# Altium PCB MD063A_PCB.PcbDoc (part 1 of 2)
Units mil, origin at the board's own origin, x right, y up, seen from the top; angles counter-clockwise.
Board outline 3360 x 2682 mil, 4 copper layers (Top Layer, Signal Layer 1, Signal Layer 2, Bottom Layer), stack 61.6 mil thick; 162 components, 89 nets, 431 pads, 221 vias.
Unrouted connection lines stored in the file: 2.
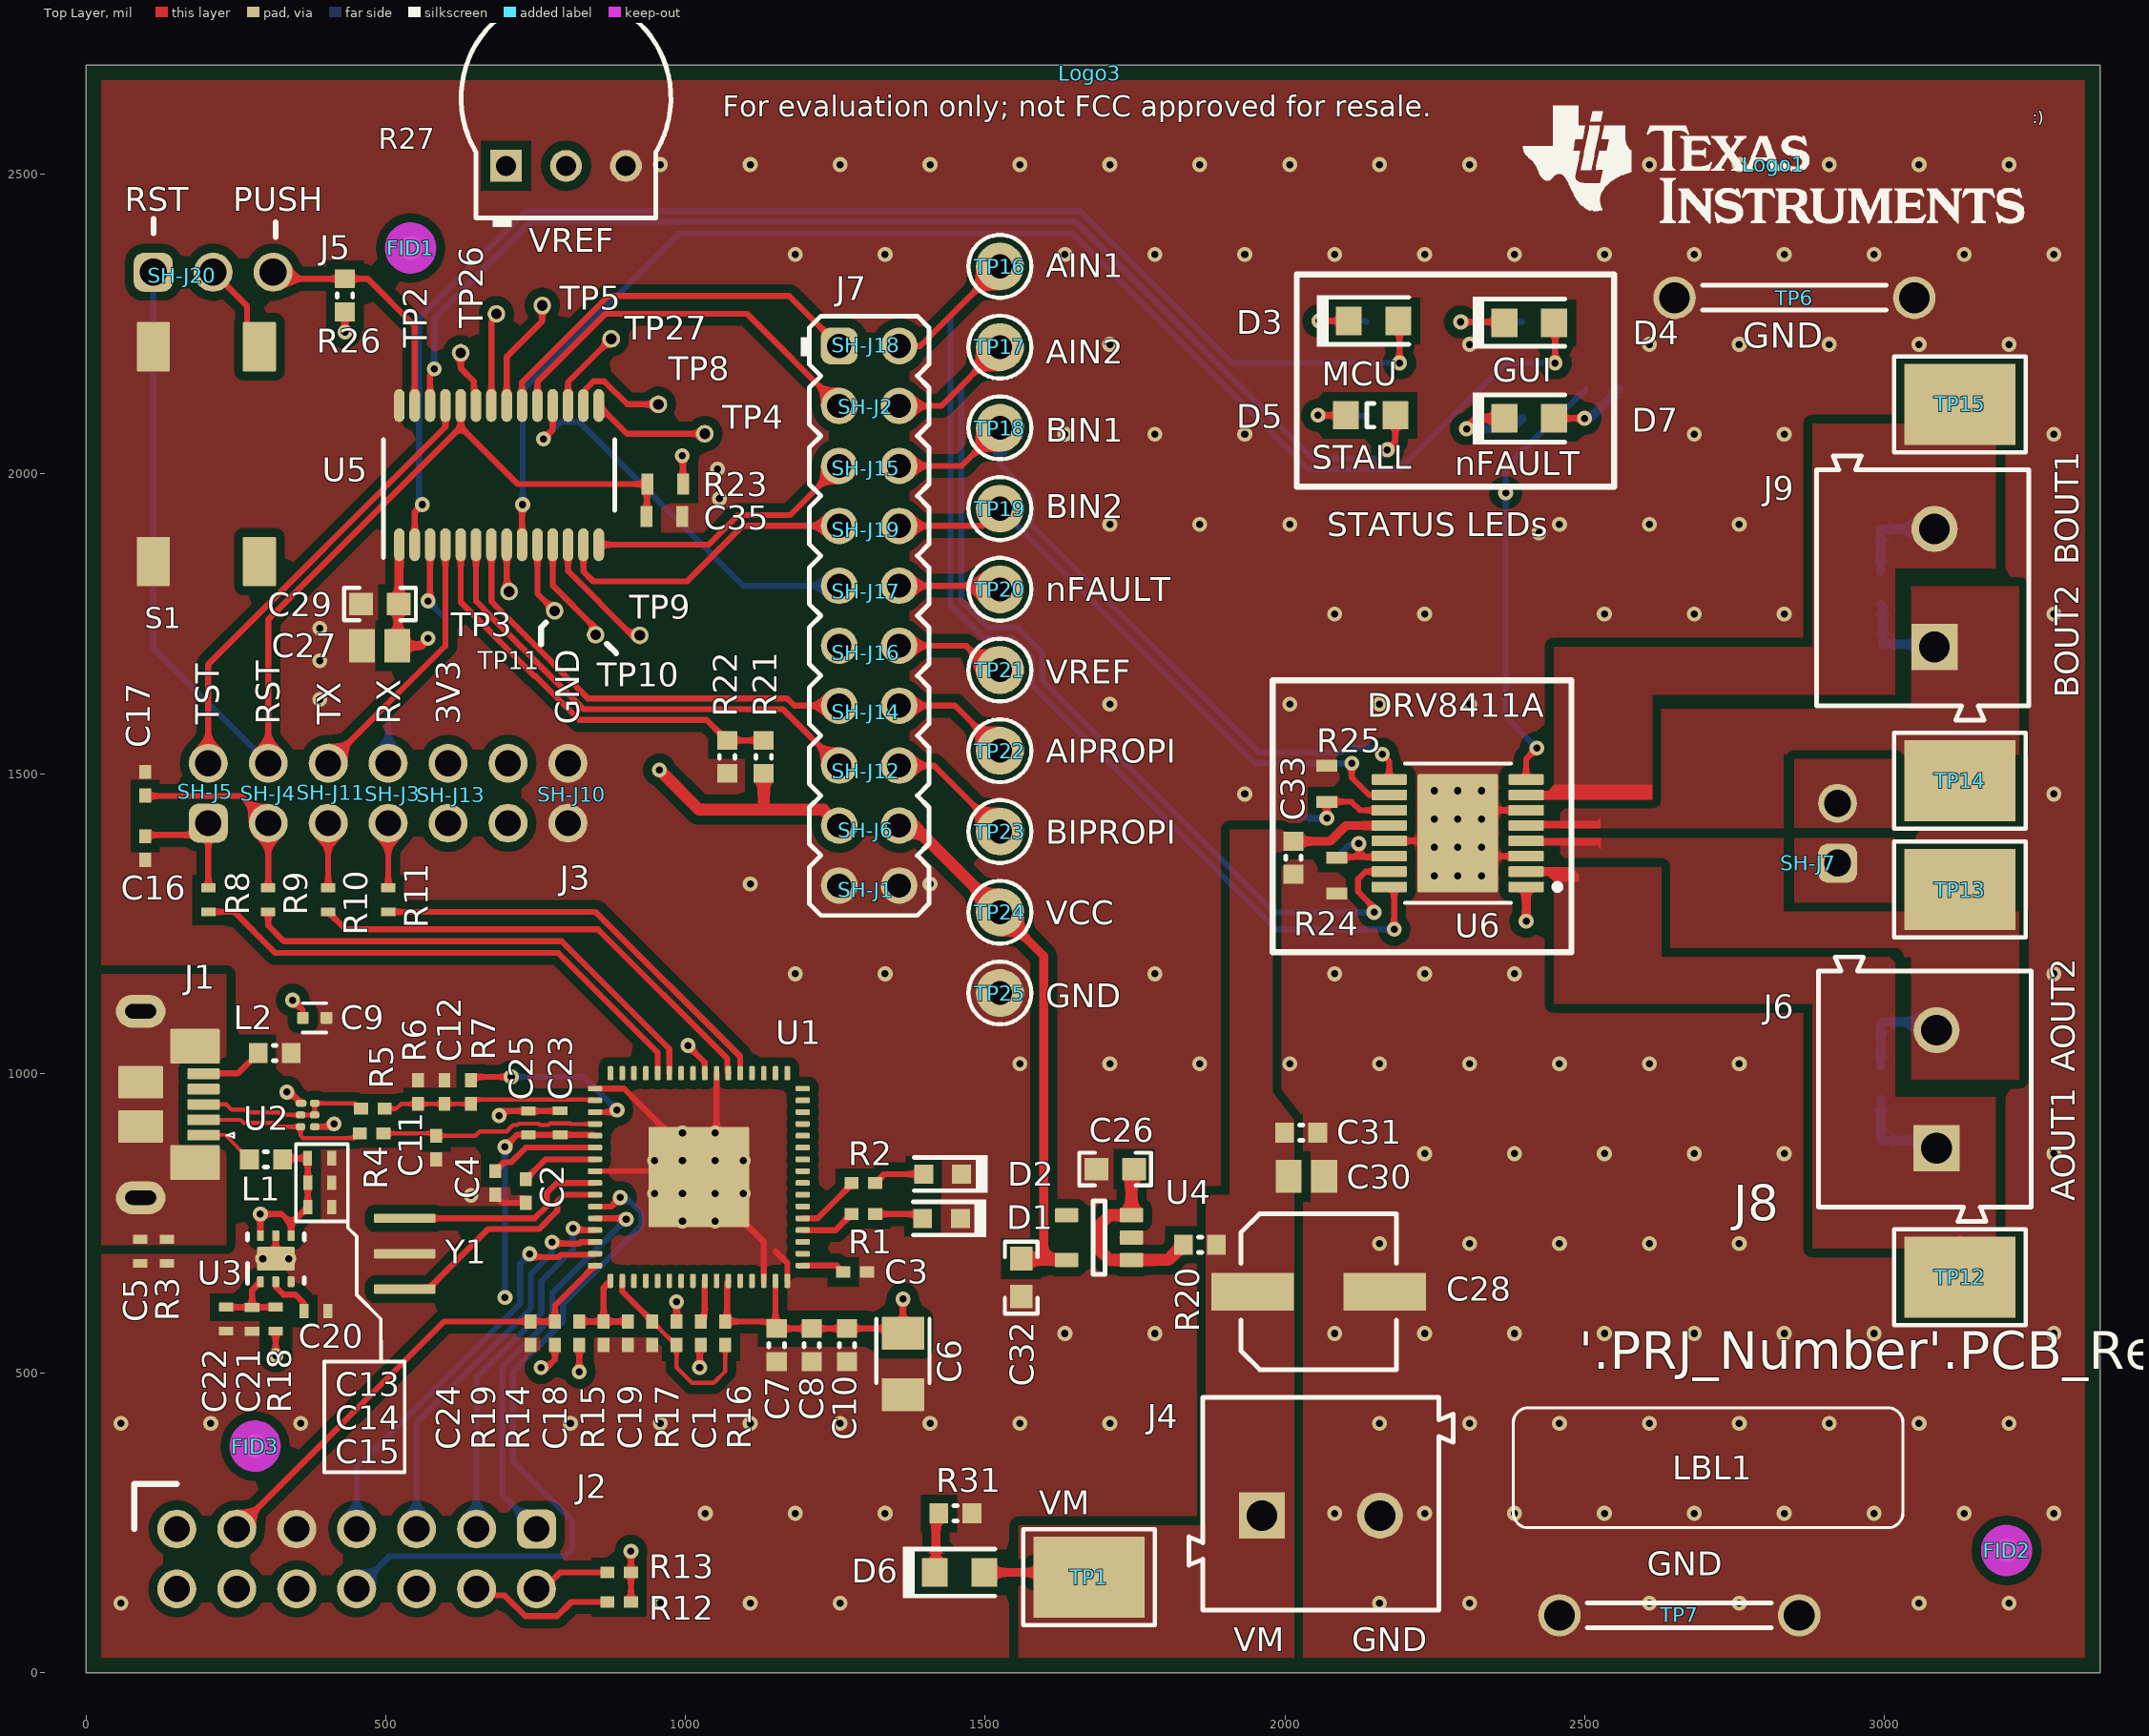
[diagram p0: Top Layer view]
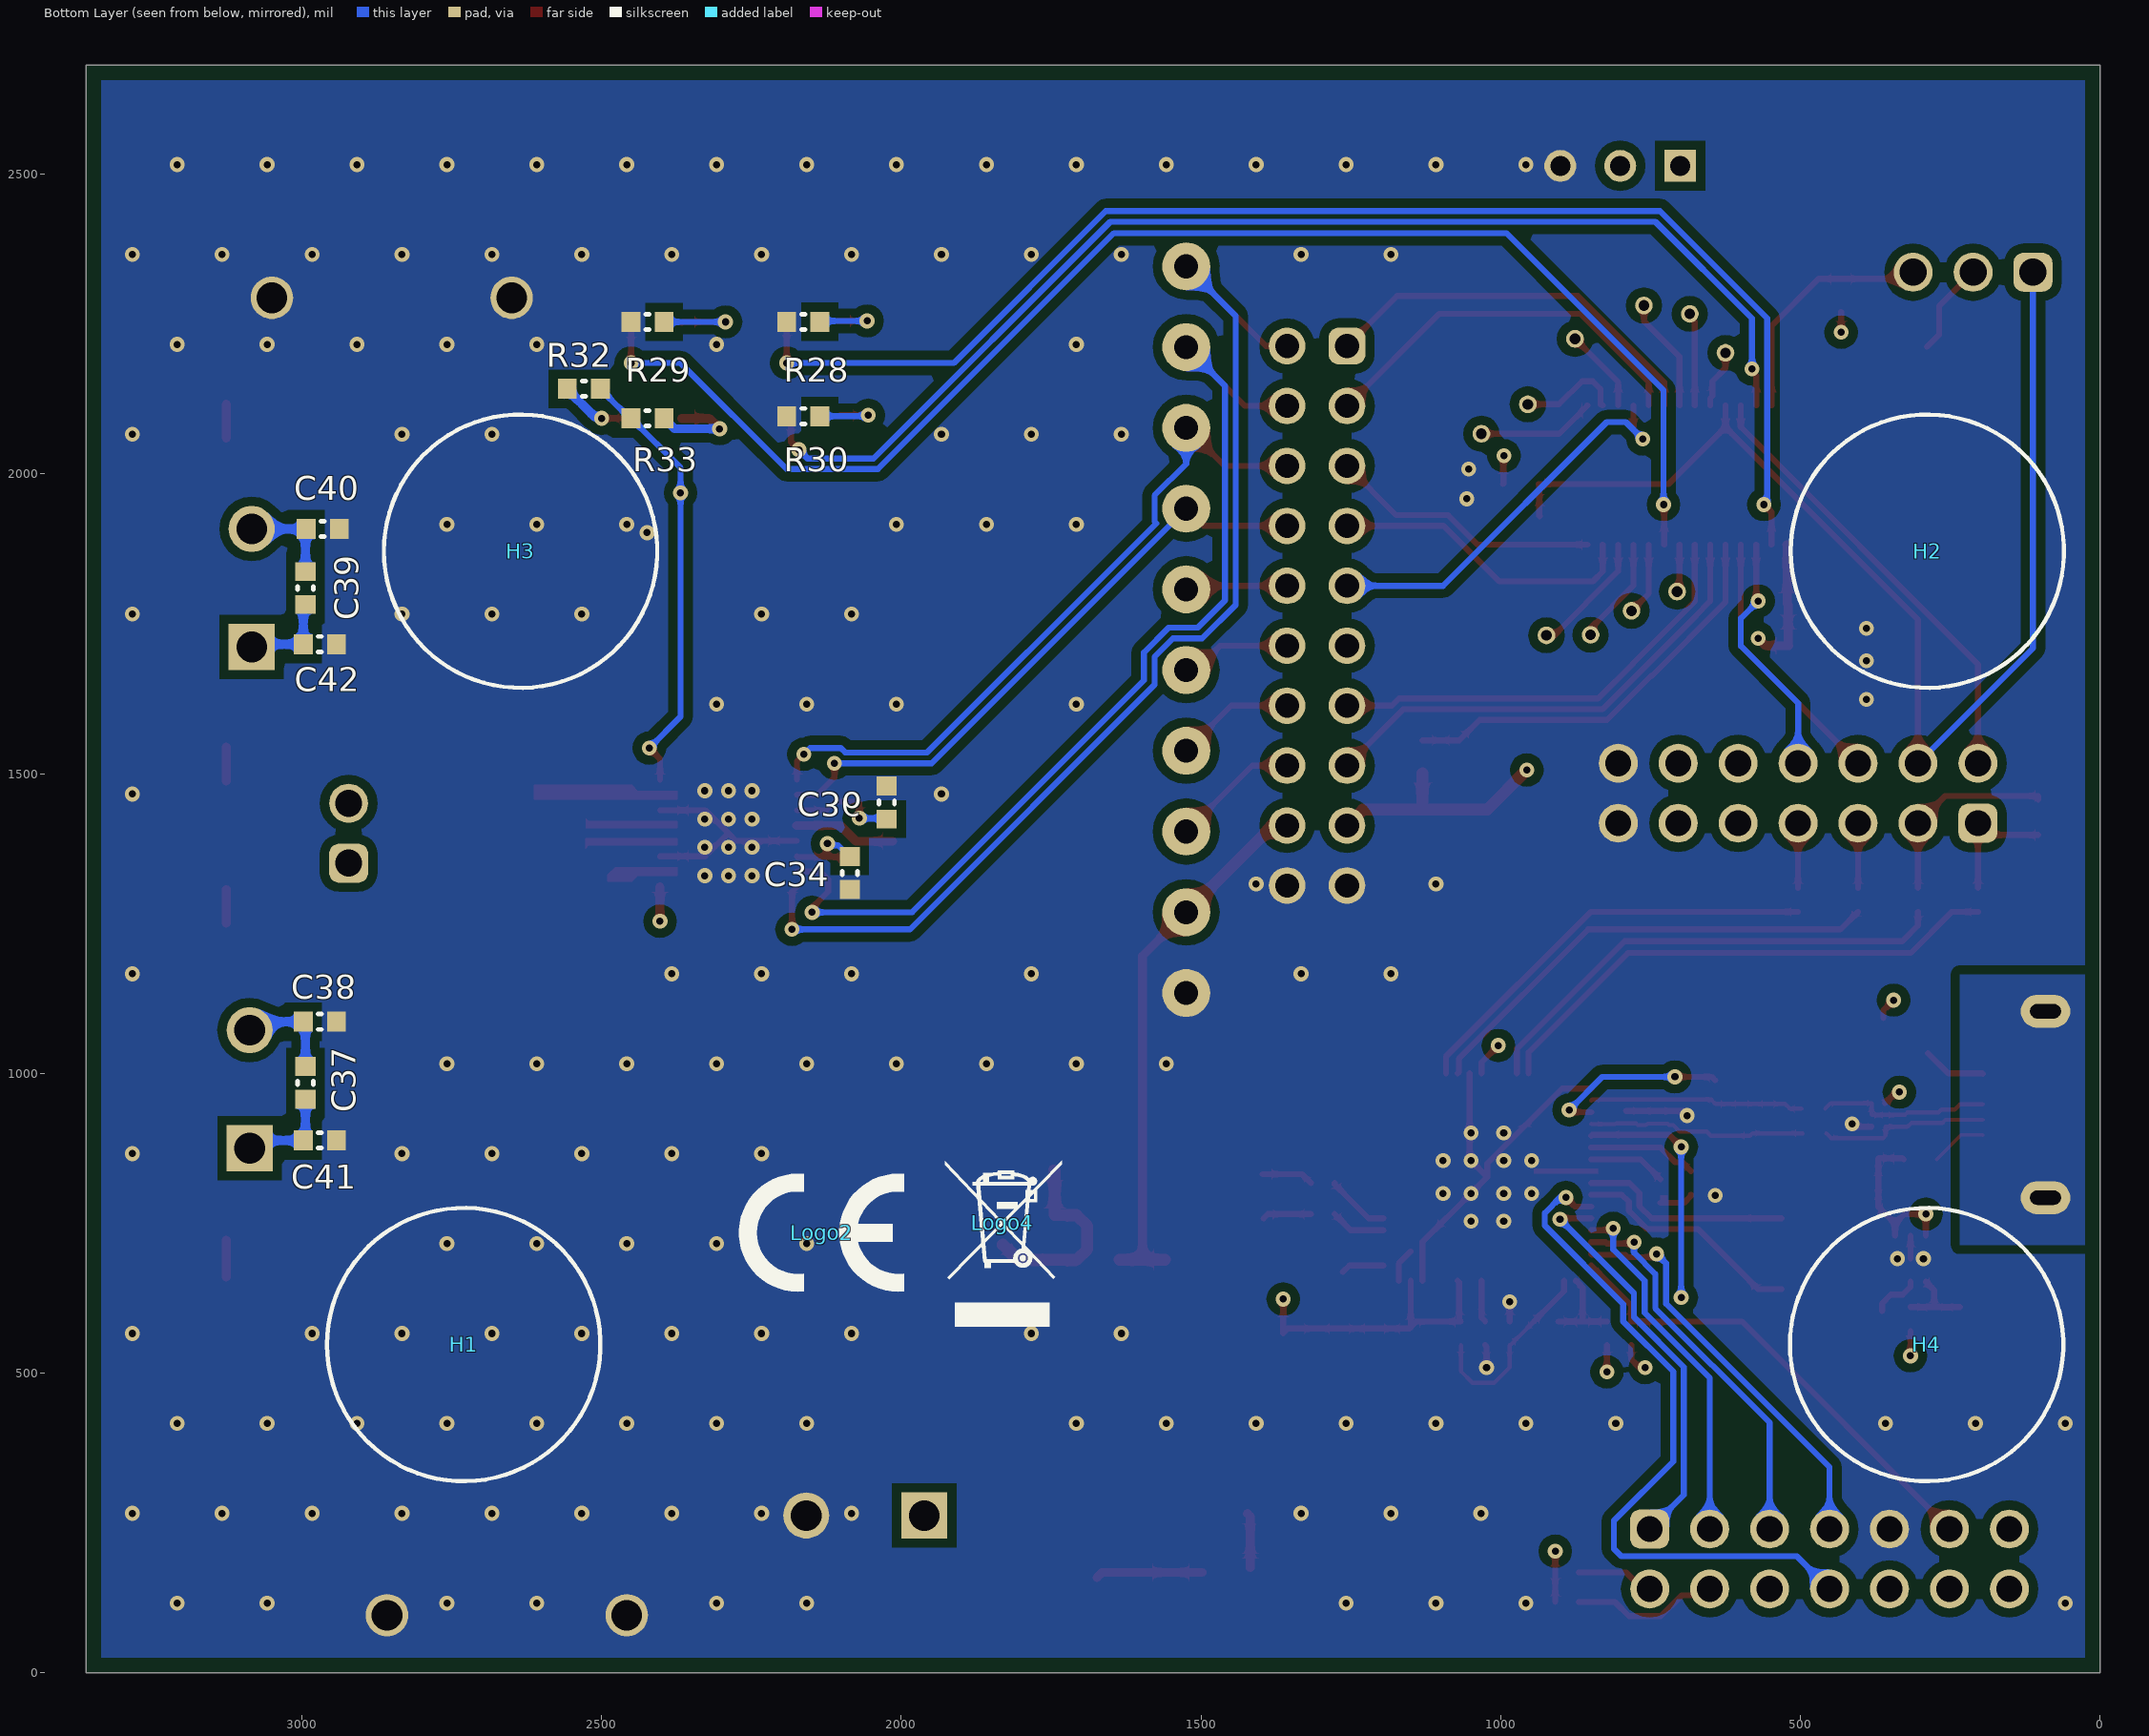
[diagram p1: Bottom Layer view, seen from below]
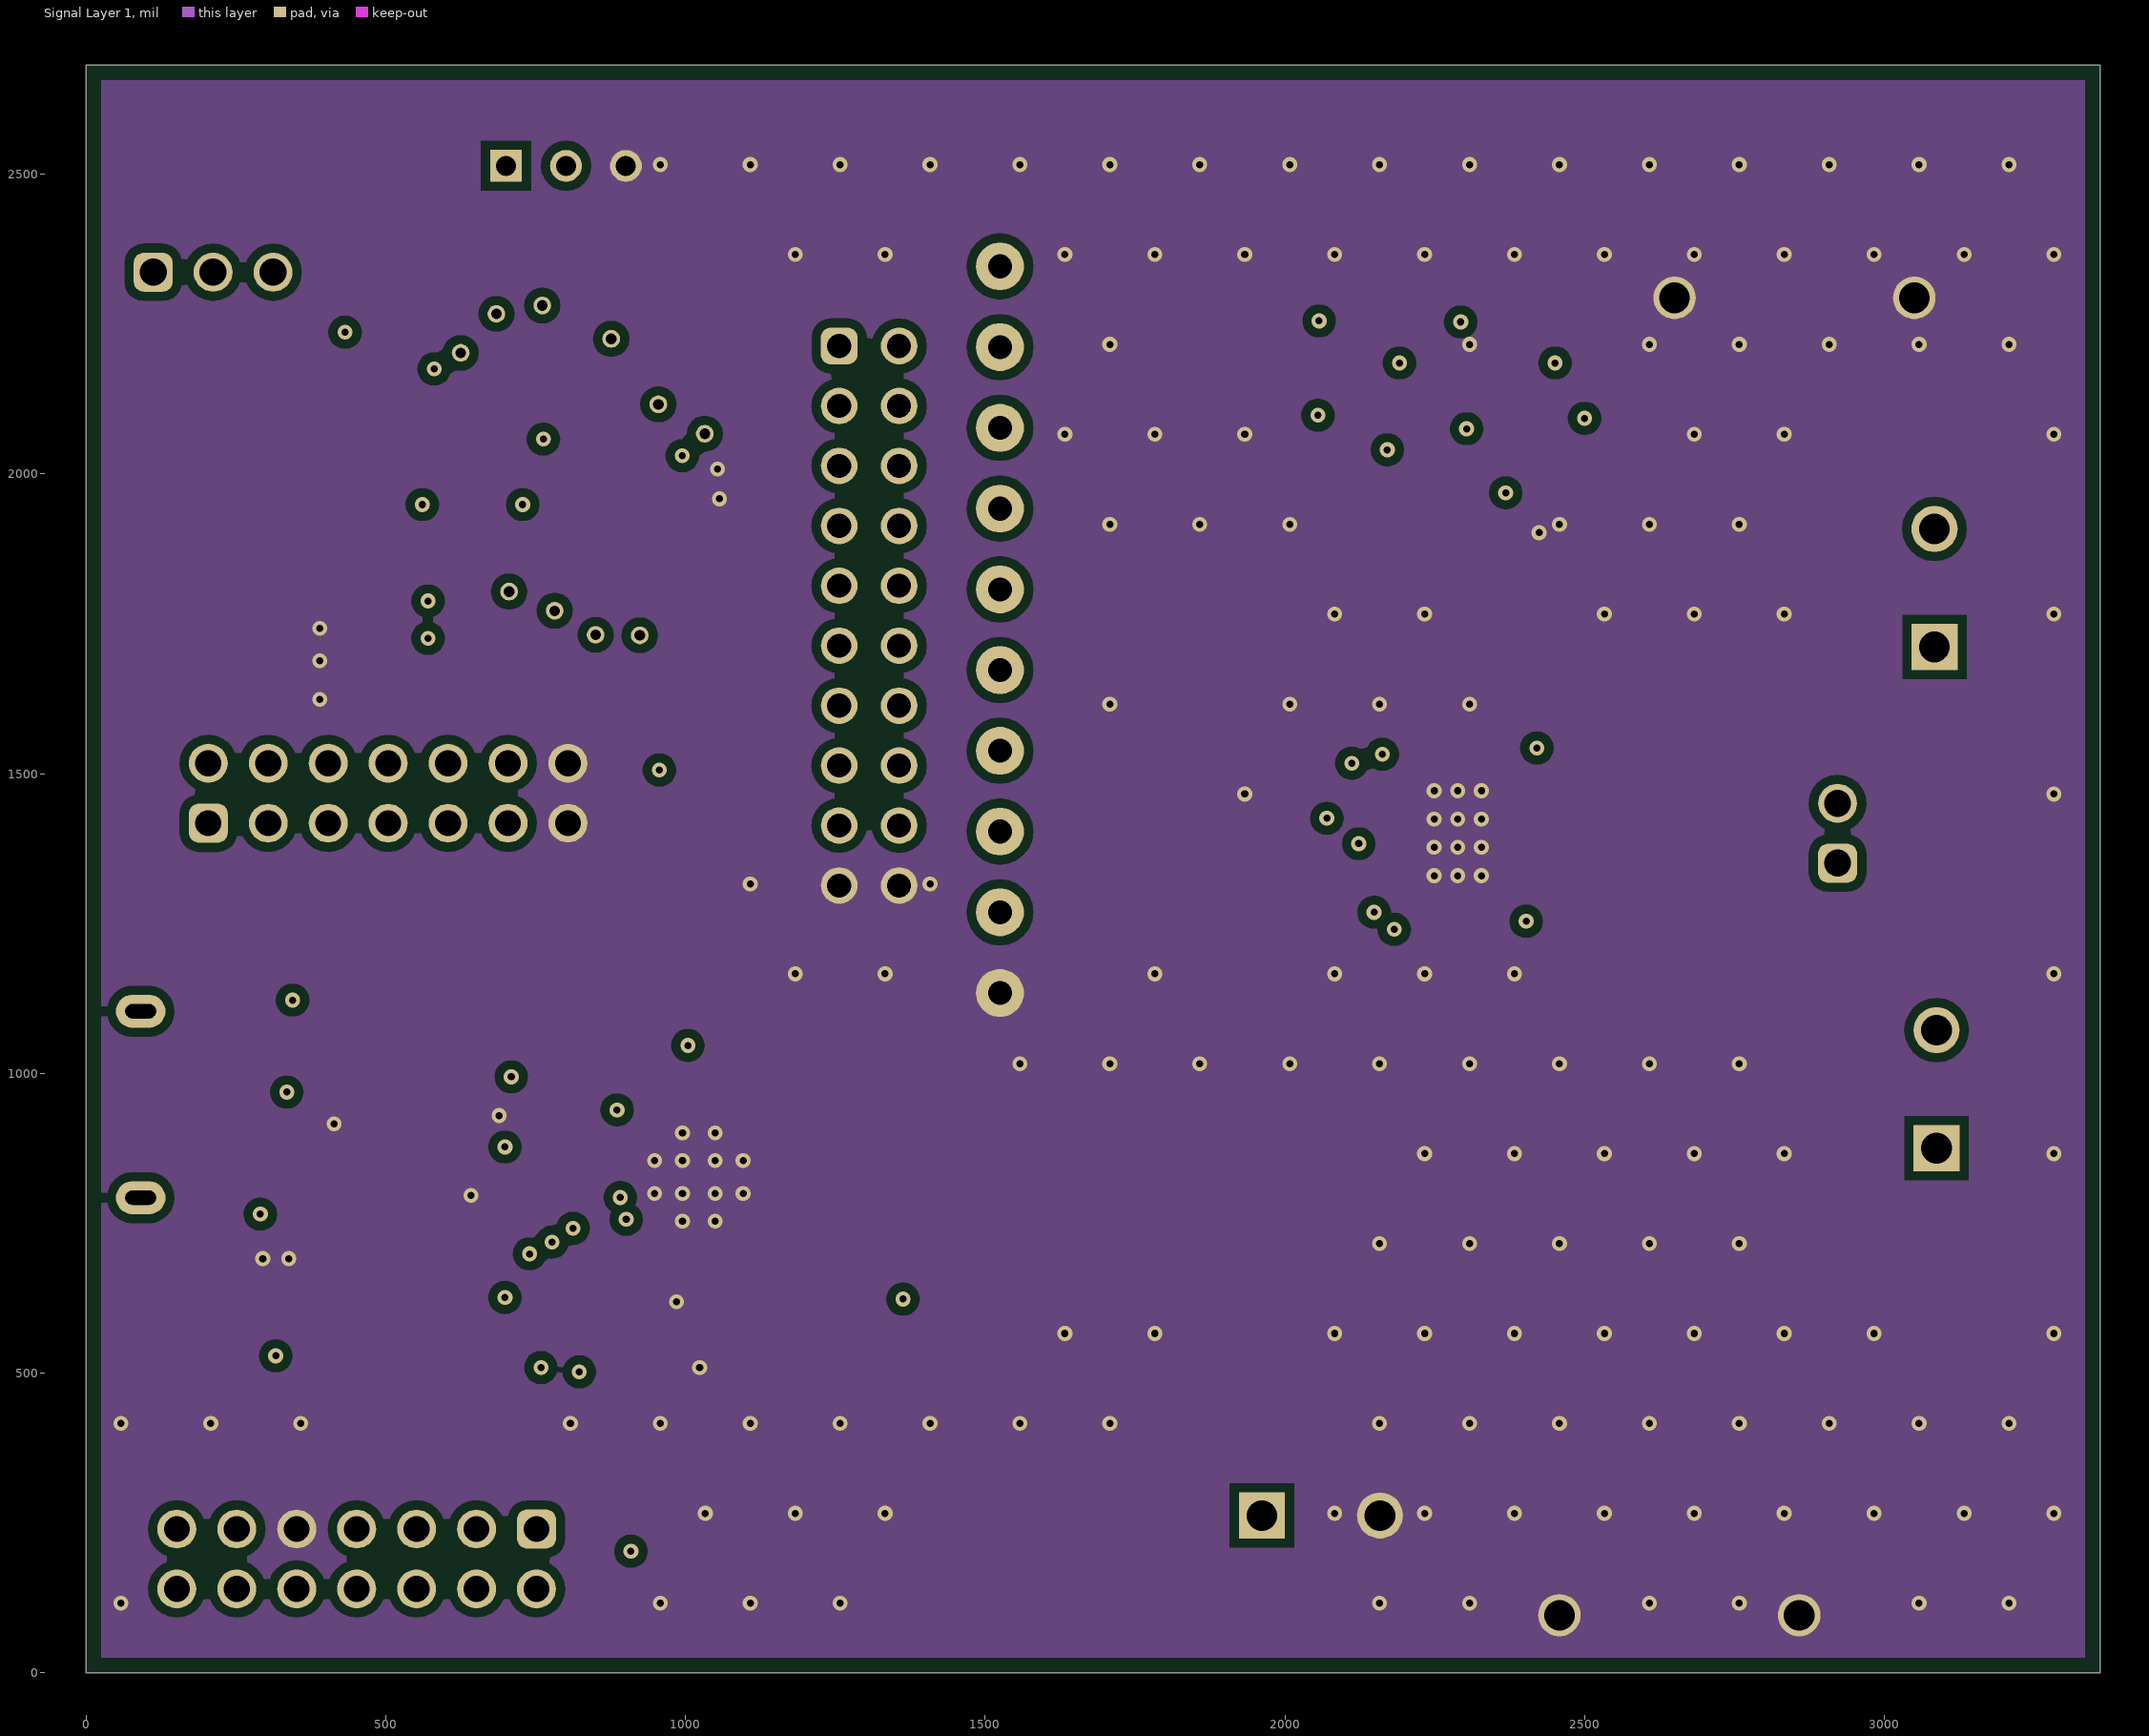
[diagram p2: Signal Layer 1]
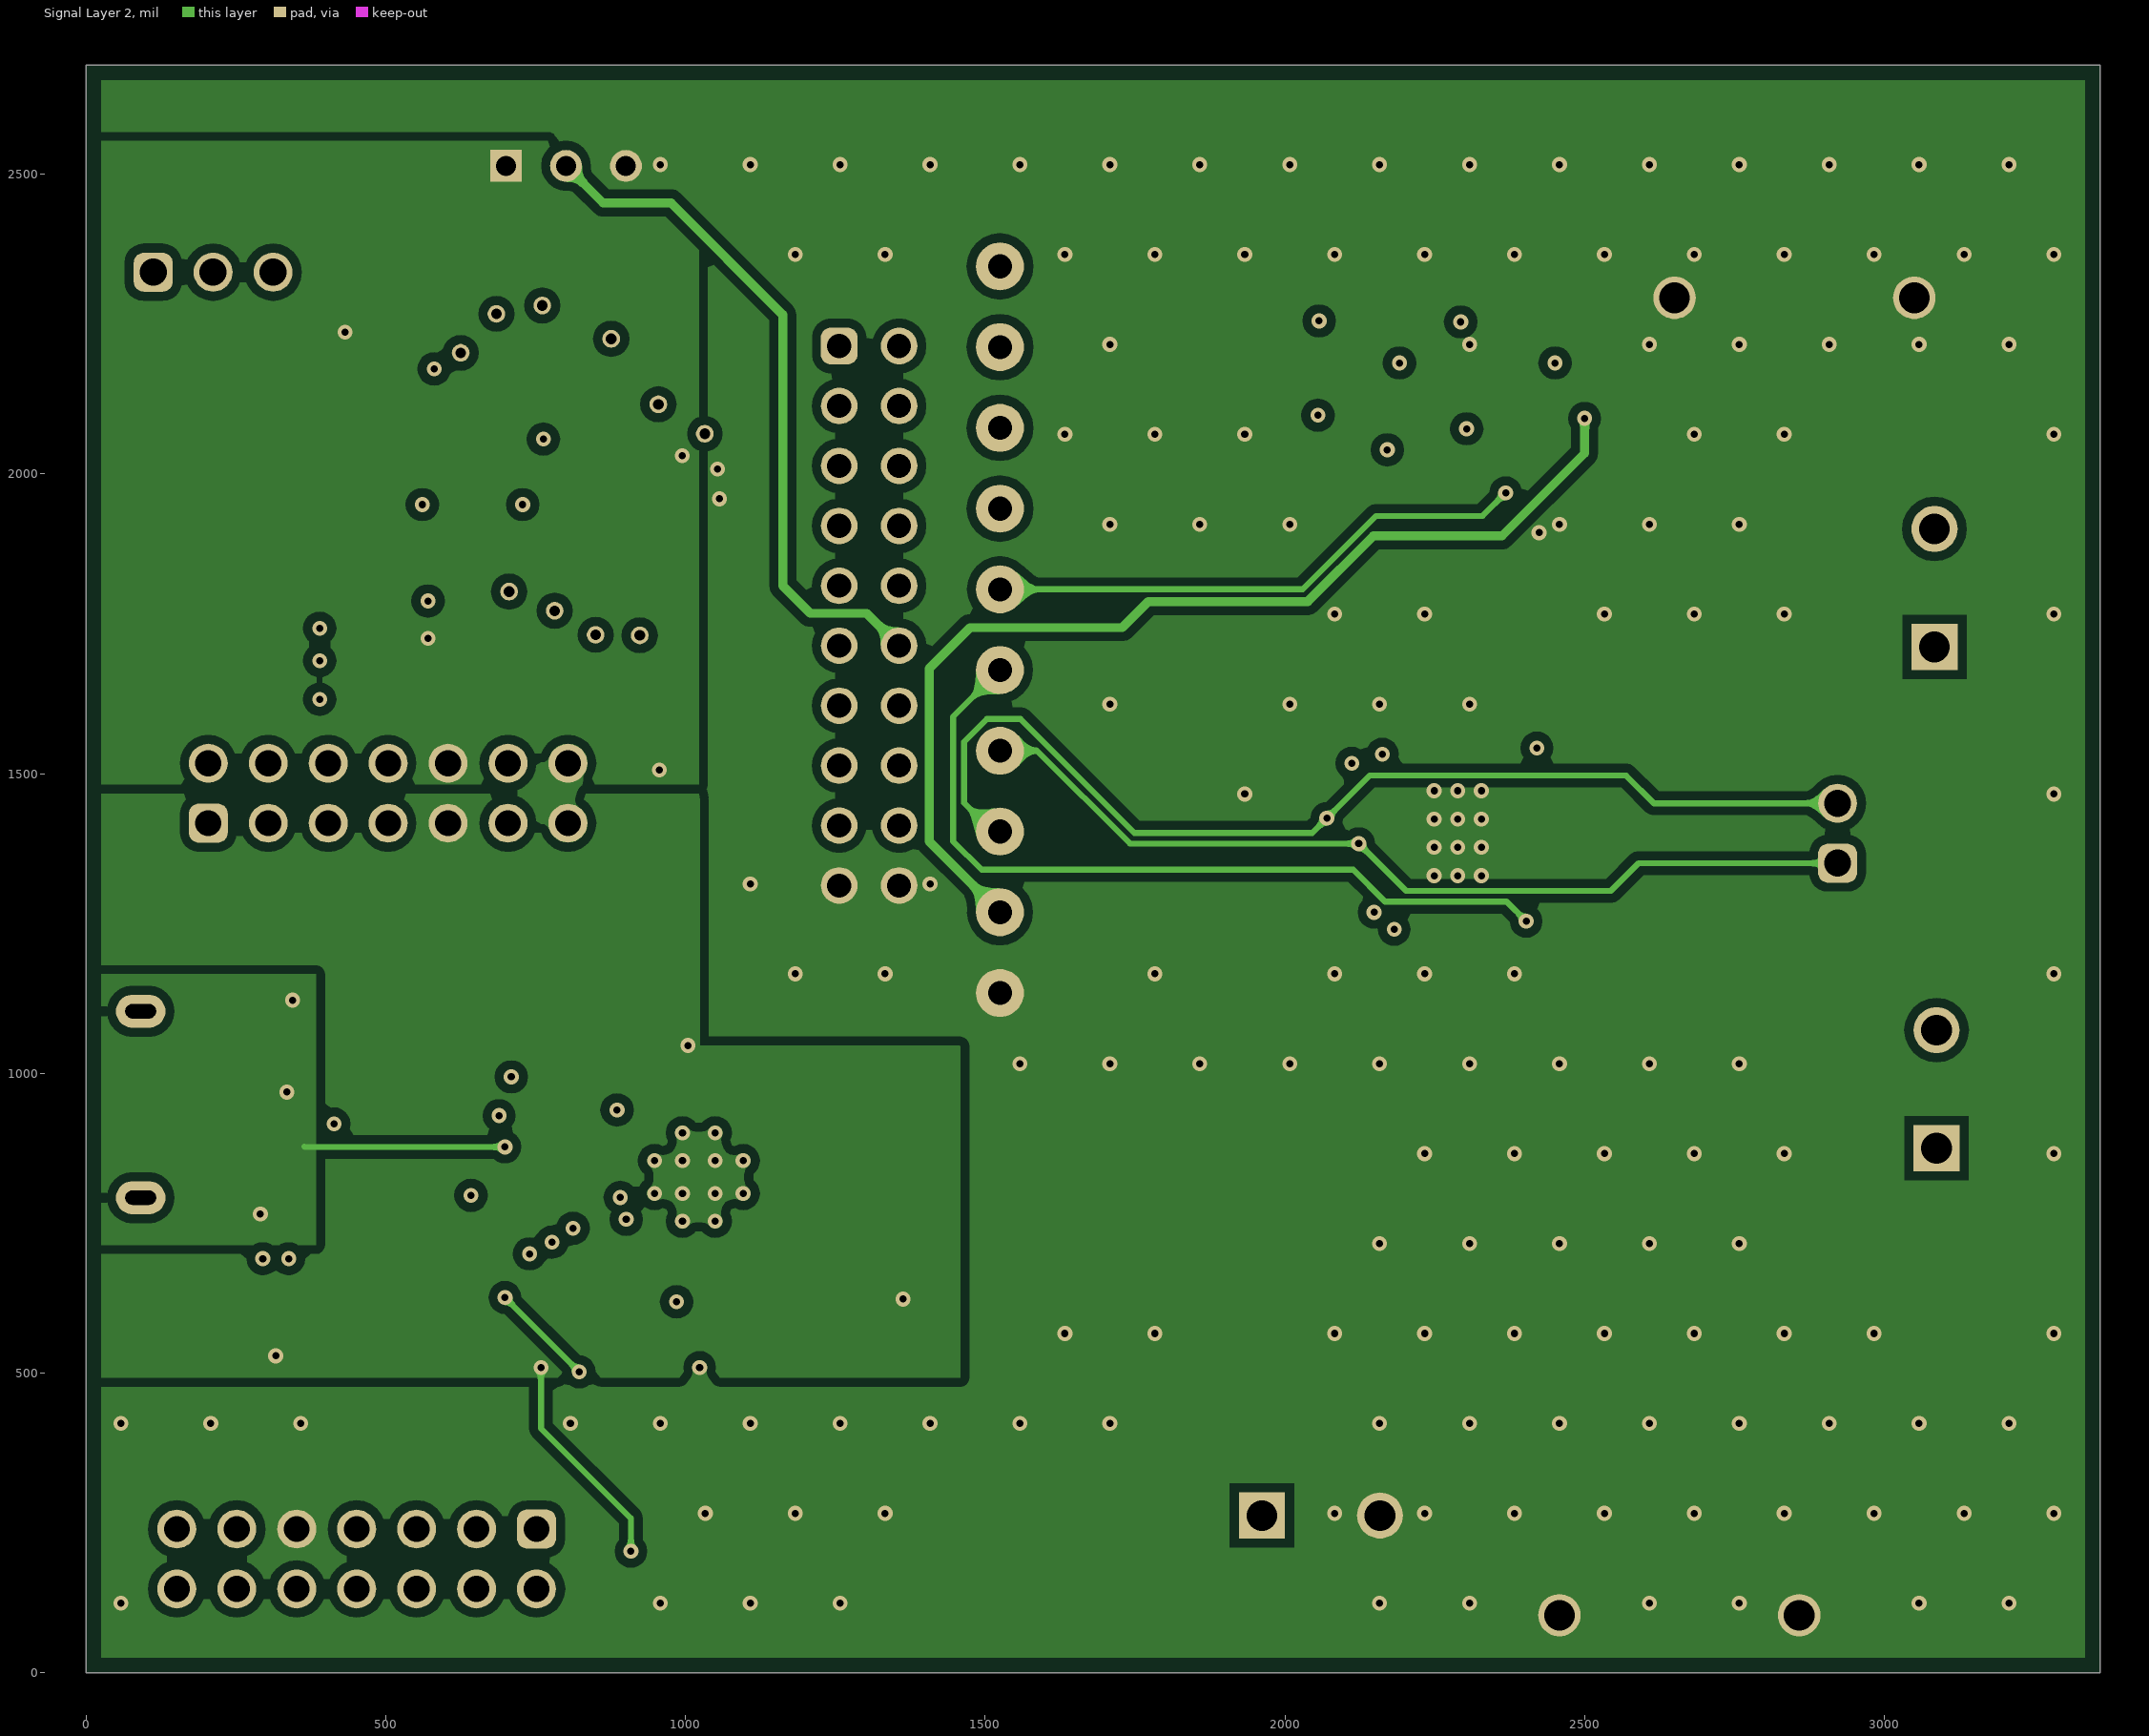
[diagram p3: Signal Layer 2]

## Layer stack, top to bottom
Top Solder: solder mask 0.4, Solder Resist, Dk 3.5
Top Layer: signal copper 2.8
Dielectric 1: prepreg 8, FR-4, Dk 4.2
Signal Layer 1: signal copper 1.4
Dielectric 2: core 37.2, FR-4, Dk 4.2
Signal Layer 2: signal copper 1.4
Dielectric 3: prepreg 8, FR-4, Dk 4.2
Bottom Layer: signal copper 2.8
Bottom Solder: solder mask 0.4, Solder Resist, Dk 3.5

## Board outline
0,0 3360,0 3360,2682 0,2682

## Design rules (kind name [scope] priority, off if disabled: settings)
AcuteAngle [All] p1: minimum=4.50000000000000E+0001 checktracksonly=FALSE
AssemblyTestPointUsage [All] p1: valid=2
BoardOutlineClearance BoardOutlineClearance_MountingHoles [OnCopper and InComponentClass('Mounting Holes')] p1: gap=39.37 ignorepadtopadclearanceinfootprint=FALSE
BoardOutlineClearance BoardOutlineClearance_Poly [OnCopper and IsPoly] p2: gap=25 ignorepadtopadclearanceinfootprint=FALSE
BoardOutlineClearance [OnCopper and Not InComponentClass('Logo') and not InComponentClass('FiducialMark') and not InRegion(1000,500,4000,800) and not InPoly] p3: gap=75 ignorepadtopadclearanceinfootprint=FALSE
Clearance Clearance_Keepouts [((IsTrack Or IsArc) And Not InPoly) And IsFree and IsKeepOut vs ((IsTrack Or IsArc) And Not InPoly) And IsFree and IsKeepOut] p1: gap=0 ignorepadtopadclearanceinfootprint=FALSE
Clearance Clearance_Poly [InPolygon] p2: gap=15 ignorepadtopadclearanceinfootprint=TRUE
Clearance Clearance_FiducialMark [IsKeepOut and InComponentClass('FiducialMark') vs IsPad and InComponentClass('FiducialMark')] p3: gap=0 ignorepadtopadclearanceinfootprint=FALSE
Clearance [All] p4: gap=7.87 ignorepadtopadclearanceinfootprint=TRUE
ComponentClearance ComponentClearance_MountingHoles_FiducialMarks [InComponentClass('Mounting Holes') vs InComponentClass('FiducialMark')] p1: gap=50 collisioncheckmode=3 verticalgap=10 showdistances=FALSE
ComponentClearance ComponentClearance_Shunt [InComponentClass('Shunt')] p2: gap=0 collisioncheckmode=3 verticalgap=0 showdistances=FALSE
ComponentClearance ComponentClearance_Logo [InComponentClass('Logo')] p3: gap=50 collisioncheckmode=3 verticalgap=10 showdistances=FALSE
ComponentClearance ComponentClearance_ScrewToNut [(HasFootprint('NY PMS 440 0025 PH')) vs (HasFootprint('Keystone_1902C'))] p4: gap=5 collisioncheckmode=3 verticalgap=10 showdistances=FALSE
ComponentClearance ComponentClearance_MountingHoles [InComponentClass('Mounting Holes')] p5: gap=250 collisioncheckmode=3 verticalgap=100000 showdistances=FALSE
ComponentClearance ComponentClearance_SmallPassives [HasFootprint('0201*') or HasFootprint('0402*') or HasFootprint('0508') or HasFootprint('0603*') or HasFootprint('0612') or HasFootprint('0805*') or HasFootprint('0815*') or HasFootprint('0830*') or HasFootprint('1206*') or HasFootprint('1210*') or HasFootprint('1808*') or HasFootprint('1812*') or HasFootprint('1825*') or HasFootprint('2010*') or HasFootprint('2220*') or HasFootprint('2225*') or HasFootprint('2512*') or HasFootprint('2728*') or HasFootprint('3518*') vs HasFootprint('0201*') or HasFootprint('0402*') or HasFootprint('0508') or HasFootprint('0603*') or HasFootprint('0612') or HasFootprint('0805*') or HasFootprint('0815*') or HasFootprint('0830*') or HasFootprint('1206*') or HasFootprint('1210*') or HasFootprint('1808*') or HasFootprint('1812*') or HasFootprint('1825*') or HasFootprint('2010*') or HasFootprint('2220*') or HasFootprint('2225*') or HasFootprint('2512*') or HasFootprint('2728*') or HasFootprint('3518*')] p6: gap=14.96 collisioncheckmode=3 verticalgap=10 showdistances=FALSE
ComponentClearance ComponentClearance_THtoSMT [IsThruComponent vs IsSMTComponent] p7: gap=40 collisioncheckmode=3 verticalgap=30 showdistances=FALSE
ComponentClearance ComponentClearance_THtoTH [IsThruComponent vs IsThruComponent] p8: gap=30 collisioncheckmode=3 verticalgap=30 showdistances=FALSE
ComponentClearance [All] p9: gap=30 collisioncheckmode=3 verticalgap=10 showdistances=FALSE
DiffPairsRouting [All] p1: maxlimit=100 minlimit=10 mostfreqgap=10 toplayer_minwidth=7 toplayer_maxwidth=15 toplayer_prefwidth=15 midlayer1_minwidth=7 midlayer1_maxwidth=15 midlayer1_prefwidth=15 midlayer2_minwidth=7 midlayer2_maxwidth=15 midlayer2_prefwidth=15 bottomlayer_minwidth=7 bottomlayer_maxwidth=15 bottomlayer_prefwidth=15 maxuncoupledlength=1000
FabricationTestPointUsage TestPointUsage [All] p1: valid=2 allowmultiple=FALSE
FabricationTestpoint Testpoint [All] p1: side=3 testpointundercomponent=TRUE minsize=40 maxsize=100 preferedsize=60 minholesize=0 maxholesize=40 preferedholesize=32 testpointgrid=1 allowsidetop=TRUE allowsidebottom=TRUE usegrid=TRUE gridtolerance=0.01
FanoutControl Fanout_LCC [IsLCC] p1: bgadir=Out bgaviamode=Centered fanoutstyle=Auto fanoutdirection=Alternating viagrid=1 // Fanout_LCC (Default Rule)
FanoutControl Fanout_BGA [IsBGA] p2: bgadir=Out bgaviamode=Centered fanoutstyle=Auto fanoutdirection=Alternating viagrid=1 // Fanout_BGA (Default Rule)
FanoutControl Fanout_Default [All] p4: bgadir=Out bgaviamode=Centered fanoutstyle=Auto fanoutdirection=Alternating viagrid=1 // Fanout_Default (Default Rule)
FanoutControl Fanout_Small [(CompPinCount < 5)] p5: bgadir=Out bgaviamode=Centered fanoutstyle=Auto fanoutdirection=OutThenIn viagrid=1 // Fanout_Small (Default Rule)
HoleSize [All] p1: absolutevalues=TRUE maxlimit=251 minlimit=7.87 maxpercent=80.000 minpercent=20.000
MinimumAnnularRing MinimumAnnularRing_ThermalPadVias [IsVia and InAnyComponent] p1: minimumring=5.91
MinimumAnnularRing [All] p2: minimumring=7.87
MinimumSolderMaskSliver MinimumSolderMaskSliver_Logo [InComponentClass('Logo') vs InComponentClass('Logo')] p1: minsoldermaskwidth=0.7
MinimumSolderMaskSliver [All] p2: minsoldermaskwidth=3.94
PlaneClearance [All] p1: clearance=15
PlaneConnect [All] p1: planeconnectstyle=Direct reliefexpansion=10 reliefentries=4 reliefconductorwidth=10 reliefairgap=10
PolygonConnect [All] p1: connectstyle=Direct reliefconductorwidth=10 reliefentries=4 polygonreliefangle="90 Angle" airgapwidth=10
RoutingVias ThermalPadVias [IsVia and InAnyComponent] p1: holewidth=12 width=26 viastyle="Through Hole" minholewidth=6 minwidth=19.68 maxholewidth=12 maxwidth=26
RoutingVias [All] p2: holewidth=16 width=34 viastyle="Through Hole" minholewidth=7.87 minwidth=26 maxholewidth=40 maxwidth=65
SilkToBoardRegionClearance [Not ((IsComment or IsDesignator) And (Hide <> 'False')) and not InRegion(1000,500,4000,800)] p1:
SilkToSilkClearance SilkToSilkClearance_Pb-FreeLogo [(HasFootprint('Pb-Free_Overlay_Medium') OR HasFootprint('Pb-Free_Overlay_Small')) vs (HasFootprint('Pb-Free_Overlay_Medium') OR HasFootprint('Pb-Free_Overlay_Small'))] p1: silktosilkclearance=0
SilkToSilkClearance [All] p2: silktosilkclearance=3.94
SilkToSolderMaskClearance SilkToComponentPadClearance [(IsPad or IsFill or IsRegion) and InAnycomponent] p1: minsilkscreentomaskgap=5 clearancetoexposedcopper=TRUE
SilkToSolderMaskClearance "Silk to Solder Mask Opening" [All] p2: minsilkscreentomaskgap=3.94 clearancetoexposedcopper=FALSE
SolderMaskExpansion [All] p1: expansion=1.97 istentingtop=FALSE
UnRoutedNet [All] p1: checkbadconnections=TRUE
Width [All] p1: maxlimit=100 minlimit=6 preferedwidth=10 checkconnectedcopper=TRUE
13 further rules are at their usual default settings.

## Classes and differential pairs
net class Power-Net: EZFET_VBUS EZFET_VCC GND VCC
component class Shunt: SH-J1 SH-J2 SH-J3 SH-J4 SH-J5 SH-J6 SH-J7 SH-J10 SH-J11 SH-J12 SH-J13 SH-J14 SH-J15 SH-J16 SH-J17 SH-J18 SH-J19 SH-J20
component class MD063A_Sch: C26 C27 C28 C29 C30 C31 C32 C33 C34 C35 C36 C37 C38 C39 C40 C41 C42 D3 D4 D5 D6 D7 J4 J5 J6 J7 J8 J9 P1.7 P2.0 P2.1 P2.2 P2.3 P3.1 P3.4 P3.7 R20 R21 R22 R23 R24 R25 R26 R27 R28 R29 R30 R31 R32 R33 S1 SH-J7 SH-J10 SH-J11 SH-J12 SH-J13 SH-J14 SH-J15 SH-J16 SH-J17 SH-J18 SH-J19 SH-J20 TP1 TP2 TP3 TP4 TP5 TP6 TP7 TP8 TP9 TP10 TP11 TP12 TP13 TP14 TP15 TP16 TP17 TP18 TP19 TP20 TP21 TP22 TP23 TP24 TP25 TP26 TP27 U4 U5 U6
component class Header: J2 J3 J5 J6 J7
component class ezFET: C1 C2 C3 C4 C5 C6 C7 C8 C9 C10 C11 C12 C13 C14 C15 C16 C17 C18 C19 C20 C21 C22 C23 C24 C25 D1 D2 J1 J2 J3 L1 L2 R1 R2 R3 R4 R5 R6 R7 R8 R9 R10 R11 R12 R13 R14 R15 R16 R17 R18 R19 SH-J1 SH-J2 SH-J3 SH-J4 SH-J5 SH-J6 U1 U2 U3 Y1
component class Logo: Logo1
component class MD063A_Hardware: FID1 FID2 FID3 H1 H2 H3 H4 LBL1 Logo1 Logo2 Logo3 Logo4 ZZ1 ZZ2 ZZ3 ZZ4
component class FiducialMark: FID1 FID2 FID3
component class AssemblyNote: ZZ1 ZZ2 ZZ3 ZZ4
component class Label: LBL1
differential pair USB_D: +USB_D_P -USB_D_N
differential pair EZFET_D: +EZFET_D_P -EZFET_D_N

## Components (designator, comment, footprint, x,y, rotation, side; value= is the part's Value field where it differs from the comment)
C1 "885012105010" 0402L 1025.83,566.33 r270 top value=0.1uF
C2 "885012105011" 0402L 733.76,803.68 r270 top value=0.22uF
C3 "GRM155R61C474KE01" 0402L 1282.97,668.69 r0 top value=0.47uF
C4 "885012105011" 0402L 682.58,817.31 r270 top value=0.22uF
C5 "885012105011" 0402S 90,702.96 r270 top value=0.22uF
C6 "T520A106M010ATE080" 3216-18 1362.73,515.14 r270 top value=10uF
C7 "885012206020" 0603L 1152.1,546.64 r270 top value=0.1uF
C8 "885012206020" 0603L 1210.65,546.64 r270 top value=0.1uF
C9 "885012205018" FP-885012205018_0402-MFG 381.4,1092.52 r180 top value=100nF
C10 "885012206020" 0603L 1269.19,546.64 r270 top value=0.1uF
C11 "885012005055" 0402L 584.15,876.17 r270 top value=10pF
C12 "885012005055" 0402L 597.93,968.69 r90 top value=10pF
C13 "885012105012" 0402S 389.59,858.4 r0 top value=1uF
C14 "885012105010" 0402S 389.9,817.46 r0 top value=0.1uF
C15 "885012205031" 0402S 389.9,776.96 r0 top value=0.01uF
C16 "885012005055" 0402L 98.69,1375.85 r90 top value=10pF
C17 "885012005055" 0402L 98.69,1483.07 r270 top value=10pF
C18 "C1005C0G1H330J050BA" 0402L 863.43,566.33 r270 top value=33pF
C19 "C1005C0G1H330J050BA" 0402L 944.63,566.33 r270 top value=33pF
C20 "885012205031" 0402S 383.68,603.41 r0 top value=0.01uF
C21 "885012105013" 0402S 276.91,589.63 r270 top value=2.2uF
C22 "885012105012" 0402S 233.76,589.95 r270 top value=1uF
C23 "C1005X5R1A475M050BC" 0402S 790.85,917.51 r90 top value=4.7uF
C24 "885012205061" 0402L 741.63,566.33 r270 top value=1000pF
C25 "GRM155R61A104KA01D" 0402S 738.19,917.26 r90 top value=0.1uF
C26 "885012206076" 0603 1716.98,840.36 r180 top value=1uF
C27 "885012207025" 0805L 489.66,1713.34 r180 top value=4.7uF
C28 "865080645012" WCAP-ASLI_630x770 2056.35,635.76 r0 top value=47uF
C29 "885012206020" 0603 490.16,1783.03 r180 top value=0.1uF
C30 "885012207103" 0805L 2035.85,827.94 r0 top value=1uF
C31 "885012206095" 0603L 2027,900.8 r0 top value=0.1uF
C32 "GRM188R61A475ME15" 0603 1559.97,659.25 r270 top value=4.7uF
C33 "885012206095" 0603L 2014.46,1359.56 r270 top value=0.1uF
C34 "885012206034" 0603L 2086.05,1334.26 r270 bottom value=1000pF
C35 "GRM1885C1E102JA01D" 0603S 964.67,1929.21 r0 top value=1000pF
C36 "885012206034" 0603L 2024.2,1451.73 r90 bottom value=1000pF
C37 "885012206083" 0603L 2994,984 r90 bottom value=1000pF
C38 "885012206083" 0603L 2970,1086 r180 bottom value=1000pF
C39 "885012206083" 0603L 2994,1809.56 r90 bottom value=1000pF
C40 "885012206083" 0603L 2965.12,1908 r180 bottom value=1000pF
C41 "885012206083" 0603L 2970,888 r180 bottom value=1000pF
C42 "885012206083" 0603L 2970,1716 r180 bottom value=1000pF
D1 "150060RS75000" WL-SMCW_RED 1427.17,757.87 r180 top value=Red
D2 "CMP-0002894-2" WL-SMCW_GREEN 1429.13,831.88 r180 top value=Green
D3 "150080VS75000" WL-SMCW_Green_0805 2147.79,2255.17 r0 top value="Bright Green"
D4 "150080VS75000" WL-SMCW_Green_0805 2407.48,2252.02 r0 top value="Bright Green"
D5 "Yellow" 0805_A 2142.87,2097.79 r0 top
D6 "150080VS75000" WL-SMCW_Green_0805 1457.16,167.32 r0 top value="Bright Green"
D7 "150080SS75000" WL-SMCW_RED_0805 2407.48,2092.67 r0 top value=Red
FID1 "Fiducial" Fiducial10-20 541.41,2376.82 r0 top
FID2 "Fiducial" Fiducial10-20 3204,204 r0 top
FID3 "Fiducial" Fiducial10-20 282,378 r0 top
H1 "SJ-5303 (CLEAR)" Bumpon_SJ5003Transparent 2730,547.45 r180 bottom
H2 "SJ-5303 (CLEAR)" Bumpon_SJ5003Transparent 288.29,1871.09 r180 bottom
H3 "SJ-5303 (CLEAR)" Bumpon_SJ5003Transparent 2635.06,1871.09 r180 bottom
H4 "SJ-5303 (CLEAR)" Bumpon_SJ5003Transparent 289.44,547.45 r180 bottom
J1 "CMP-0055311-1" Molex_1051640001 34.05,948.08 r270 top
J2 "61301421121" Wurth_61301421121 451.38,189.76 r270 top
J3 "61301421121" Wurth_61301421121 503.86,1467.32 r90 top
J4 "691101710002" 691101710002 2060.09,282 r0 top
J5 "61300311121" WURTH_61300311121 212,2336.43 r0 top
J6 "61300211121" WURTH_61300211121 2922,1400.55 r90 top
J7 "PEC10DAAN" SULLINS_PEC10DAAN 1306.4,1763.34 r0 top
J8 "691101710002" 691101710002 3067.5,973.64 r90 top
J9 "691101710002" 691101710002 3064.03,1809.81 r90 top
L1 "742792621" 0603L 300.31,856.48 r0 top value="140 ohm"
L2 "742792621" 0603L 314.66,1033.65 r0 top value="140 ohm"
LBL1 "THT-14-423-10" Label_650x200 2706,342 r0 top
Logo1 "Texas Instruments" TI_Stacked_Overlay_Small 2815.35,2516 r0 top
Logo2 "CE Mark" CE_Mark_5mm 2132.96,734.11 r180 bottom
Logo3 "FCC disclaimer" FCC_disclaimer 1674,2668.36 r0 top
Logo4 "WEEE logo" WEEE_Minimum 1831.31,749.95 r180 bottom
R1 "CRCW0402470RJNED" 0402L 1296.75,765.14 r180 top value=470
R2 "CRCW0402390RJNED" 0402L 1296.75,816.93 r180 top value=390
R3 "CRCW040233K0JNED" 0402S 135.14,702.96 r90 top value=33k
R4 "CRCW040227R0JNED" 0402L 476.38,900 r0 top value=27
R5 "CRCW040227R0JNED" 0402L 478.33,940.95 r0 top value=27
R6 "CRCW04021M00JNED" 0402L 553.64,968.69 r270 top value=1.0Meg
R7 "CRCW04021K40FKED" 0402L 642.22,968.69 r90 top value=1.40k
R8 "CRCW040210R0FKED" 0402S 203.86,1289.37 r90 top value=10.0
R9 "CRCW040210R0FKED" 0402S 303.86,1289.37 r90 top value=10.0
R10 "CRCW040210R0FKED" 0402S 403.86,1289.37 r90 top value=10.0
R11 "CRCW040210R0FKED" 0402S 504.05,1289.37 r90 top value=10.0
R12 "ERJ-2GE0R00X" 0402L 889.27,118.11 r180 top value=0
R13 "ERJ-2GE0R00X" 0402L 889.27,167.32 r180 top value=0
R14 "CRCW0402240KFKED" 0402L 822.83,566.33 r270 top value=240k
R15 "CRCW0402150KFKED" 0402L 904.03,566.32 r90 top value=150k
R16 "RC0402FR-07220KL" 0402L 1066.44,566.32 r90 top value=220k
R17 "RC0402FR-07220KL" 0402L 985.23,566.33 r270 top value=220k
R18 "CRCW04020000Z0EDHP" 0402S 316.44,589.95 r270 top value=0
R19 "CRCW040247K0JNED" 0402L 782.23,566.33 r270 top value=47k
R20 "ERJ-3GEY0R00V" 0603L 1858.27,714 r0 top value=0
R21 "CRCW06030000Z0EA" 0603L 1130.58,1527.9 r270 top value=0
R22 "CRCW06030000Z0EA" 0603L 1069.44,1527.9 r90 top value=0
R23 "RC0603JR-0747KL" 0603S 966.45,1983.03 r0 top value=47k
R24 "CRCW06031K50JNEA" 0603S 2086.73,1329.68 r90 top value=1.5k
R25 "CRCW06031K50JNEA" 0603S 2070,1483.03 r270 top value=1.5k
R26 "CRCW060347K0JNEA" 0603L 432,2297.91 r270 top value=47k
R27 "3352T-1-503LF" Bourns_3352T 800.61,2514 r0 top value=50k
R28 "CRCW0603330RJNEA" 0603L 2163.54,2253.74 r180 bottom value=330
R29 "CRCW0603330RJNEA" 0603L 2423.23,2253.54 r180 bottom value=330
R30 "CRCW0603330RJNEA" 0603L 2163.54,2096.37 r180 bottom value=330
R31 "CRCW06034K99FKEA" 0603L 1450.29,265.93 r180 top value=4.99k
R32 "CRCW060310K0JNEA" 0603L 2529.56,2142 r0 bottom value=10k
R33 "CRCW0603330RJNEA" 0603L 2423.23,2092.67 r180 bottom value=330
S1 "FSM4JSMA" SW_FSM4JSMA 200.58,2032.88 r0 top
SH-J1 "60900213421" Wurth_60900213421 1300.74,1306.7 r180 top
SH-J2 "60900213421" Wurth_60900213421 1300.74,2112.51 r180 top
SH-J3 "60900213421" Wurth_60900213421 511.81,1466.54 r270 top
SH-J4 "60900213421" Wurth_60900213421 303.64,1467.44 r270 top
SH-J5 "60900213421" Wurth_60900213421 199,1470.07 r270 top
SH-J6 "60900213421" Wurth_60900213421 1300.74,1405.39 r180 top
SH-J7 "60900213421" Wurth_60900213421 2873.17,1350.55 r0 top
SH-J10 "60900213421" Wurth_60900213421 810,1465.07 r270 top
SH-J11 "60900213421" Wurth_60900213421 408.45,1469 r270 top
SH-J12 "60900213421" Wurth_60900213421 1300.74,1504.08 r180 top
SH-J13 "60900213421" Wurth_60900213421 608.99,1464.52 r270 top
SH-J14 "60900213421" Wurth_60900213421 1300.74,1602.77 r180 top
SH-J15 "60900213421" Wurth_60900213421 1300.74,2009.75 r180 top
SH-J16 "60900213421" Wurth_60900213421 1300.74,1701.46 r180 top
SH-J17 "60900213421" Wurth_60900213421 1300.74,1804.22 r180 top
SH-J18 "60900213421" Wurth_60900213421 1300.74,2215.27 r180 top
SH-J19 "60900213421" Wurth_60900213421 1300.74,1906.99 r180 top
SH-J20 "60900213421" Wurth_60900213421 159.75,2331.24 r180 top
TP1 "5016" Testpoint_Keystone_Compact 1673.23,159.19 r0 top
TP2 "TP_H0.45P0.75" TP_H045P075 625,2201.94 r90 top
TP3 "TP_H0.45P0.75" TP_H045P075 705.71,1803.7 r90 top
TP4 "TP_H0.45P0.75" TP_H045P075 1032.16,2066.93 r90 top
TP5 "TP_H0.45P0.75" TP_H045P075 761.1,2280.91 r90 top
TP6 "CMP-0075110-1" Harwin_D3082-05 2850,2293.79 r180 top
TP7 "CMP-0075110-1" Harwin_D3082-05 2658,96 r180 top
TP8 "TP_H0.45P0.75" TP_H045P075 954.72,2116.14 r90 top
TP9 "TP_H0.45P0.75" TP_H045P075 923.65,1730.64 r90 top
TP10 "TP_H0.45P0.75" TP_H045P075 850.06,1731.55 r90 top
TP11 "TP_H0.45P0.75" TP_H045P075 781.78,1771.65 r90 top
TP12 "5016" Testpoint_Keystone_Compact 3126,660 r180 top
TP13 "5016" Testpoint_Keystone_Compact 3126,1306.7 r0 top
TP14 "5016" Testpoint_Keystone_Compact 3126,1488 r180 top
TP15 "5016" Testpoint_Keystone_Compact 3126,2116.14 r0 top
TP16 "5002" Keystone5002 1524.61,2346.22 r0 top
TP17 "5002" Keystone5002 1524.61,2211.53 r0 top
TP18 "5002" Keystone5002 1524.61,2076.84 r0 top
TP19 "5002" Keystone5002 1524.61,1942.15 r0 top
TP20 "5002" Keystone5002 1524.61,1807.46 r0 top
TP21 "5002" Keystone5002 1524.61,1672.77 r0 top
TP22 "5002" Keystone5002 1524.61,1538.08 r0 top
TP23 "5002" Keystone5002 1524.61,1403.39 r0 top
TP24 "5002" Keystone5002 1524.61,1268.7 r0 top
TP25 "5002" Keystone5002 1524.61,1134.01 r0 top
TP26 "TP_H0.45P0.75" TP_H045P075 684.48,2267 r90 top
TP27 "TP_H0.45P0.75" TP_H045P075 876.06,2225.38 r90 top
U1 "CMP-0039269-4" RGC0064B 1022.31,826.96 r90 top
U2 "TPD2E001DRYR" DRY0006A 369.59,930.5 r0 top
U3 "TPS73533DRVR" DRV0006A 316.44,690.76 r90 top
U4 "TPS70933DBVR" DBV0005A_N 1689.84,726 r180 top
U5 "MSP430G2553IPW28R" PW0028A_N 688.98,1998.03 r90 top
U6 "DRV8411APWPR" PWP0016C-MFG 2288.34,1400.55 r180 top
Y1 "CSTNR4M00GH5L000R0" MuRata_CSTNR 531.5,699 r270 top
ZZ1 "This Assembly Note is for PCB labels only" AssemblyNoteLabel 185,3938 r0 top
ZZ2 "These assemblies are ESD sensitive, ESD precautions shall be observed." AssemblyNote 185,3829.11 r0 top
ZZ3 "These assemblies must be clean and free from flux and all contaminants. Use of no clean flux is not acceptable." AssemblyNote 185,3740.56 r0 top
ZZ4 "These assemblies must comply with workmanship standards IPC-A-610 Class 2, unless otherwise specified." AssemblyNote 185,3652 r0 top

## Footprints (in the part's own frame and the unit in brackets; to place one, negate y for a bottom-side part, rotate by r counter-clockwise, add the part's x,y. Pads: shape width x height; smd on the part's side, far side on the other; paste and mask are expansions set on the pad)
0402L [mm] "0402 from SM-752 data"
  rect 0.6x0.5 smd: 1(-0.5,0) 2(0.5,0)
  body extent -0.55,-0.3 0.55,0.3, height 0.6
0402S [mil] "Based on C0402S footprint from PADS legacy"
  rect 15x24 smd: 1(-20,0) 2(20,0)
  body extent -22,-12 22,12, height 24
0603 [mm] "0603 from SM-752 data"
  rect 1x0.95 smd: 1(-0.8,0) 2(0.8,0)
  silkscreen extent -1.52,-0.69 1.52,0.69, body extent -0.87,-0.47 0.87,0.47, height 1
0603L [mm] "0603 from SM-752 data"
  rect 0.8x0.85 smd: 1(-0.7,0) 2(0.7,0)
  silkscreen extent -0.07,-0.33 0.07,0.33, body extent -0.87,-0.47 0.87,0.47, height 1
0603S [mil]
  rect 20x35 smd: 1(-30,0) 2(30,0)
  body extent -34,-19 34,19, height 39
0805_A [mm] "Chip LED, 2-Leads, Body 2.0x1.3mm, IPC Medium Density"
  rect 1.1x1.2 smd: 1(-1.05,0) 2(1.05,0)
  silkscreen extent -0.15,-0.5 0.15,0.5, body extent -1,-0.62 1,0.63, height 0.68
0805L [mm] "0805 from SM-752 data"
  rect 1.1x1.4 smd: 1(-0.75,0) 2(0.75,0)
  body extent -1.1,-0.72 1.1,0.72, height 1.45
3216-18 [mm] "Based on AVX recommendation in http://www.avx.com/download/software/literature/AVX-Footprint-Library.pdf"
  rrect7% 1.4x1.8 smd: 1(-1.3,0) 2(1.3,0)
  silkscreen extent -1.9,-1.12 0.8,1.12, body extent -1.7,-0.9 1.7,0.9, height 1.82
691101710002 [mm] "5,00mm - modular - blue - Horizontal entry with pressure clamp - 12,6mm height - 02p"
  rect 1.95x1.95 hole 1.3: 1(-2.5,-0.5)
  round 1.95 hole 1.3: 2(2.5,-0.5)
  silkscreen extent -5.6,-4.5 5.6,4.5, body extent -5.6,-4.5 5.6,4.5, height 12.65
AssemblyNote [mil] "Assembly Note"
AssemblyNoteLabel [mil] "Assembly Note for PCB Labels"
Bourns_3352T [mm] "TH, 3-Leads, Body 9.53x8.89mm, Pitch 2.54mm"
  rect 1.35x1.35 hole 0.85: 1(-2.54,0)
  round 1.35 hole 0.85: 2(0,0) 3(2.54,0)
  silkscreen extent -4.44,-2.6 4.44,7.31, body extent -4.44,-2.21 4.45,7.32, height 3.81
Bumpon_SJ5003Transparent [mil] "3M Hemispherical Bumpon transparent"
  round 1 on Mech4: 0(0,0)
  silkscreen extent -228,-228 228,228, body extent -219,-219 219,219, height 197
CE_Mark_5mm [mil] "Minimum text height for CE Mark"
  silkscreen extent -138,-98 138,98
DBV0005A_N [mm] "SOT23, 5-Leads, Body 2.9x1.6mm, Pitch 0.95mm, Lead Span 2.8mm, IPC Medium Density"
  rrect17% 1x0.6 smd: 1(-1.375,0.95) 2(-1.375,0) 3(-1.375,-0.95) 4(1.375,-0.95) 5(1.375,0.95)
  silkscreen extent -0.25,-1.55 0.25,1.55, body extent -1.42,-1.46 1.42,1.46, height 1.09
DRV0006A [mm] "SON, 6-Leads, Body 2x2mm, Pitch 0.65mm, Thermal Pad 1.6x1mm, TI Recommended"
  rrect33% 0.45x0.3 smd: 1(-0.975,0.65) 2(-0.975,0) 3(-0.975,-0.65) 4(0.975,-0.65) 5(0.975,0) 6(0.975,0.65)
  rrect14% 1x0.7 on Top Paste: 7(0,0.45) 7(0,-0.45)
  rrect10% 1x1.6 smd paste-0.5: 7(0,0)
  silkscreen extent -1.05,-1.2 1.05,1.2, body extent -1.05,-1.05 1.05,1.05, height 0.81
DRY0006A [mm] "USON-6"
  rrect67% 0.45x0.3 smd paste-0.05 mask-0.05: 1(-0.275,0.5)
  rrect67% 0.4x0.3 smd paste-0.05 mask-0.05: 2(-0.3,0) 3(-0.3,-0.5) 4(0.3,-0.5) 5(0.3,0) 6(0.3,0.5)
  body extent -0.5,-0.72 0.5,0.73, height 0.58
FCC_disclaimer [mil]
Fiducial10-20 [mm]
  round 1 smd mask+0.5: 1(0,0)
  Top Layer keep-out circle w1.178: c0,0 r0.5
FP-885012205018_0402-MFG [mm]
  rrect20% 0.5x0.5 smd paste+0 mask+0: 1(-0.5,0) 2(0.5,0)
  silkscreen extent -0.5,-0.63 0.5,0.63, body extent -0.85,-0.38 0.85,0.38, height 0.25
Harwin_D3082-05 [mm] "Shorting Plug, 10.16mm spacing, TH"
  round 1.8 hole 1.3: 1(-5.08,0) 2(5.08,0)
  silkscreen extent -3.9,-0.53 3.9,0.53, body extent -5.6,-0.52 5.61,0.52, height 6.63
Keystone5002 [mil] "For Keystone 500x miniature loop terminals"
  round 80 hole 40: 1(0,0)
  silkscreen extent -52,-52 52,52, body extent -49,-49 49,49, height 182
Label_650x200 [mil] "Thermal Transfer Label"
  round 1 on Mech13: 0(0,0)
  silkscreen extent -325,-100 325,100, body extent -325,-100 325,100, height 1
Molex_1051640001 [mm] "Receptacle, USB 2.0, Micro B, 5 Pos, 0.65mm Pitch, R/A, SMT"
  rrect22% 0.45x1.38 smd: 1(1.3,4.11) 2(0.65,4.11) 3(0,4.11) 4(-0.65,4.11) 5(-1.3,4.11)
  rrect7% 1.475x2.1 smd: 6(-2.462,3.75) 11(2.462,3.75)
  rrect100% 1.4x2.1 hole 0.6 slot 1.3 at 90 deg: 7(-3.95,1.45) 10(3.95,1.45)
  rrect7% 1.375x1.9 smd: 8(-0.937,1.45) 9(0.937,1.45)
  silkscreen extent 1.2,5.1 1.4,5.4, body extent -4.1,-0.7 4.1,4.47, height 2.45
MuRata_CSTNR [mm] "SMD, 3-Leads, Body 4.5x2mm, Pitch 1.5mm"
  rrect25% 0.4x2.6 smd: 1(-1.5,0) 2(0,0) 3(1.5,0)
  body extent -2.3,-1.05 2.3,1.05, height 1.2
PW0028A_N [mm] "TSOP, 28-Leads, Body 9.7x4.4mm, Pitch 0.65mm, IPC Medium Density"
  oval 1.4x0.45 smd: 1(-2.95,4.225) 2(-2.95,3.575) 3(-2.95,2.925) 4(-2.95,2.275) 5(-2.95,1.625) 6(-2.95,0.975) 7(-2.95,0.325) 8(-2.95,-0.325) 9(-2.95,-0.975) 10(-2.95,-1.625) 11(-2.95,-2.275) 12(-2.95,-2.925) 13(-2.95,-3.575) 14(-2.95,-4.225) 15(2.95,-4.225) 16(2.95,-3.575) 17(2.95,-2.925) 18(2.95,-2.275) 19(2.95,-1.625) 20(2.95,-0.975) 21(2.95,-0.325) 22(2.95,0.325) 23(2.95,0.975) 24(2.95,1.625) 25(2.95,2.275) 26(2.95,2.925) 27(2.95,3.575) 28(2.95,4.225)
  silkscreen extent -3.5,-4.9 1.5,4.9, body extent -3.21,-4.85 3.21,4.85, height 1
PWP0016C-MFG [mm]
  rrect22% 1.5x0.45 smd paste+0 mask+0: 1(-2.9,2.275) 2(-2.9,1.625) 3(-2.9,0.975) 4(-2.9,0.325) 5(-2.9,-0.325) 6(-2.9,-0.975) 7(-2.9,-1.625) 8(-2.9,-2.275) 9(2.9,-2.275) 10(2.9,-1.625) 11(2.9,-0.975) 12(2.9,-0.325) 13(2.9,0.325) 14(2.9,0.975) 15(2.9,1.625) 16(2.9,2.275)
  rrect3% 3.4x5 smd paste-1000 mask-1000: 17(0,0)
  silkscreen extent -4.35,-2.95 2.25,2.95, body extent -3.75,-2.8 3.75,2.8, height 0.25
RGC0064B [mm] "VQFN-64"
  rrect42% 0.6x0.24 smd mask+0.07: 1(-4.4,3.75) 2(-4.4,3.25) 3(-4.4,2.75) 4(-4.4,2.25) 5(-4.4,1.75) 6(-4.4,1.25) 7(-4.4,0.75) 8(-4.4,0.25) 9(-4.4,-0.25) 10(-4.4,-0.75) 11(-4.4,-1.25) 12(-4.4,-1.75) 13(-4.4,-2.25) 14(-4.4,-2.75) 15(-4.4,-3.25) 16(-4.4,-3.75) 33(4.4,-3.75) 34(4.4,-3.25) 35(4.4,-2.75) 36(4.4,-2.25) 37(4.4,-1.75) 38(4.4,-1.25) 39(4.4,-0.75) 40(4.4,-0.25) 41(4.4,0.25) 42(4.4,0.75) 43(4.4,1.25) 44(4.4,1.75) 45(4.4,2.25) 46(4.4,2.75) 47(4.4,3.25) 48(4.4,3.75)
  rrect42% 0.24x0.6 smd mask+0.07: 17(-3.75,-4.4) 18(-3.25,-4.4) 19(-2.75,-4.4) 20(-2.25,-4.4) 21(-1.75,-4.4) 22(-1.25,-4.4) 23(-0.75,-4.4) 24(-0.25,-4.4) 25(0.25,-4.4) 26(0.75,-4.4) 27(1.25,-4.4) 28(1.75,-4.4) 29(2.25,-4.4) 30(2.75,-4.4) 31(3.25,-4.4) 32(3.75,-4.4) 49(3.75,4.4) 50(3.25,4.4) 51(2.75,4.4) 52(2.25,4.4) 53(1.75,4.4) 54(1.25,4.4) 55(0.75,4.4) 56(0.25,4.4) 57(-0.25,4.4) 58(-0.75,4.4) 59(-1.25,4.4) 60(-1.75,4.4) 61(-2.25,4.4) 62(-2.75,4.4) 63(-3.25,4.4) 64(-3.75,4.4)
  rrect2% 4.25x4.25 smd paste-2.112: 65(0,0)
  body extent -4.5,-4.5 4.5,4.5, height 1
SULLINS_PEC10DAAN [mm] "SULLINS"
  rrect50% 1.55x1.55 hole 1.016: 1(-1.27,11.43)
  round 1.55 hole 1.016: 2(1.27,11.43) 3(-1.27,8.89) 4(1.27,8.89) 5(-1.27,6.35) 6(1.27,6.35) 7(-1.27,3.81) 8(1.27,3.81) 9(-1.27,1.27) 10(1.27,1.27) 11(-1.27,-1.27) 12(1.27,-1.27) 13(-1.27,-3.81) 14(1.27,-3.81) 15(-1.27,-6.35) 16(1.27,-6.35) 17(-1.27,-8.89) 18(1.27,-8.89) 19(-1.27,-11.43) 20(1.27,-11.43)
  silkscreen extent -2.9,-12.7 2.54,12.7, body extent -2.54,-12.7 2.54,12.7, height 8.38
SW_FSM4JSMA [mm] "Alcoswitch"
  rrect7% 1.4x2.1 smd: 1(2.25,4.55) 2(2.25,-4.55) 3(-2.25,4.55) 4(-2.25,-4.55)
  body extent -3,-5 3,5, height 5.09
Testpoint_Keystone_Compact [mil] "Compact SMT test point"
  rect 185x135 smd: 1(0,0)
  silkscreen extent -110,-80 110,80, body extent -75,-56 75,56, height 91
TI_Stacked_Overlay_Small [mil]
  silkscreen extent -418,-98 418,98
TP_H045P075 [mm] "TP_H0.45P0.75"
  round 0.75 hole 0.45: 1(0,0)
WCAP-ASLI_630x770 [mm] "SMD, 2-Leads, Dia 6.3mm"
  rect 3.5x1.6 smd: 1(-2.8,0) 2(2.8,0)
  silkscreen extent -3.3,-3.3 3.3,3.3, body extent -3.3,-3.3 3.3,3.3, height 7.7
WEEE_Minimum [mil] "WEEElie bin"
  silkscreen extent -95,-172 99,104
WL-SMCW_GREEN [mm] "WURTH"
  rect 0.8x0.8 smd: 1(-0.8,0) 2(0.8,0)
  silkscreen extent -1.9,-0.8 1.2,0.8, body extent -0.85,-0.45 0.85,0.45, height 0.8
WL-SMCW_Green_0805 [mm] "SMD, 2-Leads, Body 2x1.25mm"
  rect 1.1x1.2 smd: 1(-1.05,0) 2(1.05,0)
  silkscreen extent -2.4,-1.1 1.5,1.1, body extent -1,-0.62 1,0.63, height 0.7
WL-SMCW_RED [mm] "WURTH"
  rect 0.8x0.8 smd: 1(-0.8,0) 2(0.8,0)
  silkscreen extent -1.9,-0.8 1.2,0.8, body extent -0.85,-0.45 0.85,0.45, height 0.8
WL-SMCW_RED_0805 [mm] "SMD, 2-Leads, Body 1.6x0.8mm"
  rect 1.1x1.2 smd: 1(-1.05,0) 2(1.05,0)
  silkscreen extent -2.4,-1.1 1.5,1.1, body extent -1,-0.62 1,0.63, height 0.7
Wurth_60900213421 [mil] "Shunt, 2.54mm, Black"
  round 1 on Mech3: 0(0,0)
  body extent -98,-48 98,48, height 338
WURTH_61300211121 [mm] "Header, 2.54mm, 2x1, TH"
  rrect50% 1.65x1.65 hole 1.15: 1(-1.27,0)
  round 1.65 hole 1.15: 2(1.27,0)
  body extent -2.54,-1.27 2.54,1.27, height 8.54
WURTH_61300311121 [mm] "Header, 2.54mm, 3x1, TH"
  rrect50% 1.65x1.65 hole 1.15: 1(-2.54,0)
  round 1.65 hole 1.15: 2(0,0) 3(2.54,0)
  body extent -3.81,-1.27 3.81,1.27, height 8.54
Wurth_61301421121 [mm] "Header, 2.54mm, 7x2, TH"
  rrect50% 1.65x1.65 hole 1.1: 1(-1.27,7.62)
  round 1.65 hole 1.1: 2(1.27,7.62) 3(-1.27,5.08) 4(1.27,5.08) 5(-1.27,2.54) 6(1.27,2.54) 7(-1.27,0) 8(1.27,0) 9(-1.27,-2.54) 10(1.27,-2.54) 11(-1.27,-5.08) 12(1.27,-5.08) 13(-1.27,-7.62) 14(1.27,-7.62)
  body extent -2.54,-8.89 2.54,8.89, height 8.55

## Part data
C1 C14: library part CMP-0006221-2, "CAP, CERM, 0.1 uF, 10 V, +/- 20%, X5R, 0402", Cap_Case=0402, Manufacturer="Wurth Elektronik", Supplier Part Number 1=732-7487-1-ND, TempCo=X5R, Tolerance_%=20%, Value1=Unknown, Value2=10V, ValueDisplayed=0.1uF
C2 C4 C5: library part CMP-0078875-1, "CAP, CERM, 0.22 µF, 10 V,+/- 20%, X5R, 0402", Cap_Case=0402, Manufacturer="Wurth Elektronik", Supplier Part Number 1=732-7488-1-ND, TempCo=X5R, Tolerance_%=20%, Value2=10V, ValueDisplayed=0.22µF
C3: library part CMP-0006600-2, "CAP, CERM, 0.47 uF, 16 V, +/- 10%, X5R, 0402", Cap_Case=0402, Manufacturer=MuRata, TempCo=X5R, Tolerance_%=10%, Value1=Unknown, Value2=16V, ValueDisplayed=0.47uF
C6: library part CMP-0084376-1, "CAP, Tantalum Polymer, 10 µF, 10 V,+/- 20%, 0.08 ohm, 3216-18 SMD", Cap_Case=3216-18, Manufacturer=Kemet, Tolerance_%=20%, Value1="0.08 ohm", Value2=10V, ValueDisplayed=10µF
C7 C8 C10 C29: library part CMP-0064931-4, "CAP, CERM, 0.1 uF, 10 V,+/- 10%, X7R, 0603", Cap_Case=0603, Manufacturer="Wurth Elektronik", Supplier Part Number 1=732-7939-1-ND, TempCo=X7R, Tolerance_%=10%, Value1=Unknown, Value2=10V, ValueDisplayed=0.1uF
C9: library part CMP-0090362-1, "0.1µF ±10% 10V Ceramic Capacitor X7R 0402 (1005 Metric)", Digikey Part Number=732-7513-1-ND, Manufacturer="Wurth Electronics", Mouser Part Number=710-885012205018, Operating Temperature Range="-55°C to +125°C", TempCo=15%, Temperature Characteristic=X7R, Tolerance_%=10%, ValueDisplayed=100000pF
C11 C12 C16 C17: library part CMP-0006215-2, "CAP, CERM, 10 pF, 50 V, +/- 5%, C0G/NP0, 0402", Cap_Case=0402, Manufacturer="Wurth Elektronik", Supplier Part Number 1=732-7469-1-ND, TempCo=C0G/NP0, Tolerance_%=5%, Value1=Unknown, Value2=50V, ValueDisplayed=10pF
C13 C22: library part CMP-0064924-2, "CAP, CERM, 1 uF, 10 V,+/- 20%, X5R, 0402", Cap_Case=0402, Manufacturer="Wurth Elektronik", Supplier Part Number 1=732-7489-1-ND, TempCo=X5R, Tolerance_%=20%, Value1=Unknown, Value2=10V, ValueDisplayed=1uF
C15 C20: library part CMP-0006227-2, "CAP, CERM, 0.01 uF, 16 V, +/- 10%, X7R, 0402", Cap_Case=0402, Manufacturer="Wurth Elektronik", Supplier Part Number 1=710-885012205031, TempCo=X7R, Tolerance_%=10%, Value1=Unknown, Value2=16V, ValueDisplayed=0.01uF
C18 C19: library part CMP-0006250-2, "CAP, CERM, 33 pF, 50 V, +/- 5%, C0G/NP0, 0402", Cap_Case=0402, Manufacturer=TDK, Supplier Part Number 1=445-1241-1-ND, TempCo=C0G/NP0, Tolerance_%=5%, Value1=Unknown, Value2=50V, ValueDisplayed=33pF
C21: library part CMP-0006222-2, "CAP, CERM, 2.2 uF, 10 V, +/- 20%, X5R, 0402", Cap_Case=0402, Manufacturer="Wurth Elektronik", Supplier Part Number 1=710-885012105013, TempCo=X5R, Tolerance_%=20%, Value1=Unknown, Value2=10V, ValueDisplayed=2.2uF
C23: library part CMP-0006269-2, "CAP, CERM, 4.7 uF, 10 V, +/- 20%, X5R, 0402", Cap_Case=0402, Manufacturer=TDK, Supplier Part Number 1=445-8023-1-ND, TempCo=X5R, Tolerance_%=20%, Value1=Unknown, Value2=10V, ValueDisplayed=4.7uF
C24: library part CMP-0006231-2, "CAP, CERM, 1000 pF, 50 V, +/- 10%, X7R, 0402", Cap_Case=0402, Manufacturer="Wurth Elektronik", Supplier Part Number 1=732-7556-1-ND, TempCo=X7R, Tolerance_%=10%, Value1=Unknown, Value2=50V, ValueDisplayed=1000pF
C25: library part CMP-0006562-2, "CAP, CERM, 0.1 uF, 10 V, +/- 10%, X5R, 0402", Cap_Case=0402, Manufacturer=MuRata, Supplier Part Number 1=490-1318-1-ND, TempCo=X5R, Tolerance_%=10%, Value1=Unknown, Value2=10V, ValueDisplayed=0.1uF
C26: library part CMP-0006833-4, "CAP, CERM, 1 uF, 25 V, +/- 10%, X7R, 0603", Cap_Case=0603, Manufacturer="Wurth Elektronik", Supplier Part Number 1=732-7994-1-ND, TempCo=X7R, Tolerance_%=10%, Value1=Unknown, Value2=25V, ValueDisplayed=1uF
C27: library part CMP-0007690-2, "CAP, CERM, 4.7 uF, 10 V, +/- 10%, X7R, 0805", Cap_Case=0805, Manufacturer="Wurth Elektronik", Supplier Part Number 1=710-885012207025, TempCo=X7R, Tolerance_%=10%, Value1=Unknown, Value2=10V, ValueDisplayed=4.7uF
C28: library part CMP-0011161-2, "CAP, AL, 47 uF, 50 V, +/- 20%, SMD", Cap_Case=6.3x7.7mm, Manufacturer="Wurth Elektronik", Supplier Part Number 1=732-8457-1-ND, Tolerance_%=20%, Value1=Unknown, Value2=50V, ValueDisplayed=47uF
C30: library part CMP-0007696-2, "CAP, CERM, 1 uF, 50 V, +/- 10%, X7R, 0805", Cap_Case=0805, Manufacturer="Wurth Elektronik", Supplier Part Number 1=710-885012207103, TempCo=X7R, Tolerance_%=10%, Value1=Unknown, Value2=50V, ValueDisplayed=1uF
C31 C33: library part CMP-0006837-4, "CAP, CERM, 0.1 uF, 50 V, +/- 10%, X7R, 0603", Cap_Case=0603, Manufacturer="Wurth Elektronik", TempCo=X7R, Tolerance_%=10%, Value1=Unknown, Value2=50V, ValueDisplayed=0.1uF
C32: library part CMP-0007330-5, "CAP, CERM, 4.7 uF, 10 V, +/- 20%, X5R, 0603", Cap_Case=0603, Manufacturer=MuRata, Supplier Part Number 1=490-10478-1-ND, TempCo=X5R, Tolerance_%=20%, Value1=Unknown, Value2=10V, ValueDisplayed=4.7uF
C34 C36: library part CMP-0006826-4, "CAP, CERM, 1000 pF, 16 V, +/- 10%, X7R, 0603", Cap_Case=0603, Manufacturer="Wurth Elektronik", Supplier Part Number 1=710-885012206034, TempCo=X7R, Tolerance_%=10%, Value1=Unknown, Value2=16V, ValueDisplayed=1000pF
C35: library part CMP-0007159-4, "CAP, CERM, 1000 pF, 25 V, +/- 5%, C0G/NP0, 0603", Cap_Case=0603, Manufacturer=MuRata, Supplier Part Number 1=GRM1885C1E102JA01D-ND, TempCo=C0G/NP0, Tolerance_%=5%, Value1=Unknown, Value2=25V, ValueDisplayed=1000pF
C37 C38 C39 C40 C41 C42: library part CMP-0064933-4, "CAP, CERM, 1000 pF, 50 V,+/- 10%, X7R, 0603", Cap_Case=0603, Manufacturer="Wurth Elektronik", Supplier Part Number 1=732-8001-1-ND, TempCo=X7R, Tolerance_%=10%, Value1=Unknown, Value2=50V, ValueDisplayed=1000pF
D1: library part CMP-0002947-3, "LED, Red, SMD", Color=Red, Manufacturer="Wurth Elektronik", Power_TotalModule=72mW, Value1=0.072W, Value2=2V
D2: "LED, Green, SMD", Color=green, Manufacturer="Wurth Elektronik", PartNumber=150060VS75000, Value1=W, Value2=2V
D3 D4 D6: library part CMP-0002960-2, "LED, Bright Green, SMD", Color="Bright Green", Manufacturer="Wurth Elektronik", Power_TotalModule=72mW, Supplier Part Number 1=732-4986-1-ND, Value1=0.072W, Value2=2V
D5: library part CMP-1426-00012-1, "SMD mono-color Chip LED, WL-SMCW, Yellow", Manufacturer="Wuerth Elektronik", PartNumber=150080YS75000
D7: library part CMP-0002951-3, "LED, Red, SMD", Color=Red, Manufacturer="Wurth Elektronik", Power_TotalModule=72mW, Value1=0.072W, Value2=1.9V
FID1 FID2 FID3: library part CMP-0077181-1, "Fiducial mark.  There is nothing to buy or mount.", Manufacturer=N/A
H1 H2 H3 H4: library part CMP-0003620-1, "Bumpon, Hemisphere, 0.44 X 0.20, Clear", Manufacturer=3M, Supplier Part Number 1=SJ5303-7-ND
J1: "Receptacle, USB 2.0, Micro B, 5 Position, R/A, SMT", Color=Black, Current_A=1.8A, Manufacturer=Molex, PartNumber=1051640001, Supplier Part Number 1=WM11263CT-ND, Voltage_V=30V
J2 J3: library part CMP-0086014-1, "Header, 2.54mm, 7x2, Gold, TH", Color=Black, Current_A=3A, Manufacturer="Wurth Elektronik", Voltage_V=250V
J4 J8 J9: library part CMP-1502-03256-1, "Series 101 - 5.00 mm Horizontal Entry Modular with Pressure Clamp WR-TBL, 2 pin", Manufacturer="Wurth Elektronik", Operating Temperature=-40to105degC
J5: library part CMP-0054796-4, "Header, 2.54 mm, 3x1, Gold, TH", Manufacturer="Wurth Elektronik", Supplier Part Number 1=732-5316-ND
J6: library part CMP-0054794-2, "Header, 2.54 mm, 2x1, Gold, TH", Color=Black, Manufacturer="Wurth Elektronik", Supplier Part Number 1=732-5315-ND
J7: library part CMP-0054623-2, "Header, 2.54mm, 10x2, Tin, TH", Color=Black, Current_A=3A, Manufacturer="Sullins Connector Solutions", Supplier Part Number 1=S2012E-10-ND
L1 L2: library part CMP-0003184-2, "Ferrite Bead, 140 ohm @ 100 MHz, 0.55 A, 0603", Manufacturer="Wurth Elektronik", Supplier Part Number 1=732-4663-1-ND, Value1="0.2 ohm", Value2=0.55A, ValueDisplayed="140 ohm"
LBL1: library part CMP-0003625-1, "Thermal Transfer Printable Labels, 0.650\" W x 0.200\" H - 10,000 per roll", Manufacturer=Brady, Supplier Part Number 1=97C5133
Logo1: library part CMP-0074838-1, "Texas Instrument Corporate Signature"
Logo2: library part CMP-0074844-1
Logo3: library part CMP-0074847-1, "FCC_disclaimer"
Logo4: library part CMP-0074769-3, Manufacturer="Texas Instruments"
R1: library part CMP-0026934-3, "RES, 470, 5%, 0.063 W, AEC-Q200 Grade 0, 0402", Manufacturer=Vishay-Dale, Power_W=63mW, Supplier Part Number 1=541-470JCT-ND, TempCo="200 ppm/C", Tolerance_%=5%, Value2=0.063W, Value_Code=470R, ValueDisplayed=470
R2: library part CMP-0026914-3, "RES, 390, 5%, 0.063 W, AEC-Q200 Grade 0, 0402", Manufacturer=Vishay-Dale, Power_W=63mW, Supplier Part Number 1=541-390JCT-ND, TempCo="200 ppm/C", Tolerance_%=5%, Value2=0.063W, Value_Code=390R, ValueDisplayed=390
R3: library part CMP-0026907-3, "RES, 33 k, 5%, 0.063 W, AEC-Q200 Grade 0, 0402", Manufacturer=Vishay-Dale, Power_W=63mW, Supplier Part Number 1=541-33KJCT-ND, TempCo="200 ppm/C", Tolerance_%=5%, Value2=0.063W, Value_Code=33k0, ValueDisplayed=33k
R4 R5: library part CMP-0026888-3, "RES, 27, 5%, 0.063 W, AEC-Q200 Grade 0, 0402", Manufacturer=Vishay-Dale, Power_W=63mW, Supplier Part Number 1=541-27JCT-ND, TempCo="200 ppm/C", Tolerance_%=5%, Value2=0.063W, Value_Code=27R0, ValueDisplayed=27
R6: library part CMP-0026859-2, "RES, 1.0 M, 5%, 0.063 W, AEC-Q200 Grade 0, 0402", Manufacturer=Vishay-Dale, Power_W=63mW, Supplier Part Number 1=541-1.0MJCT-ND, TempCo="200 ppm/C", Tolerance_%=5%, Value2=0.063W, Value_Code=1M00, ValueDisplayed=1.0M
R7: library part CMP-0026085-3, "RES, 1.40 k, 1%, 0.063 W, AEC-Q200 Grade 0, 0402", Manufacturer=Vishay-Dale, Power_W=63mW, Supplier Part Number 1=541-1.40KLCT-ND, TempCo="100 ppm/C", Tolerance_%=1%, Value2=0.063W, Value_Code=1k40, ValueDisplayed=1.40k
R8 R9 R10 R11: library part CMP-0025963-3, "RES, 10.0, 1%, 0.063 W, AEC-Q200 Grade 0, 0402", Manufacturer=Vishay-Dale, Power_W=63mW, Supplier Part Number 1=541-10.0LCT-ND, TempCo="100 ppm/C", Tolerance_%=1%, Value2=0.063W, Value_Code=10R0, ValueDisplayed=10.0
R12 R13: library part CMP-0026992-3, "RES, 0, 5%, 0.1 W, AEC-Q200 Grade 0, 0402", Manufacturer=Panasonic, Power_W=100mW, Supplier Part Number 1=P0.0JCT-ND, TempCo="600 ppm/C", Tolerance_%=5%, Value2=0.1W, Value_Code=0000, ValueDisplayed=0
R14: library part CMP-0026190-2, "RES, 240 k, 1%, 0.063 W, AEC-Q200 Grade 0, 0402", Manufacturer=Vishay-Dale, Power_W=63mW, Supplier Part Number 1=541-240KLCT-ND, TempCo="100 ppm/C", Tolerance_%=1%, Value2=0.063W, Value_Code=240k
R15: library part CMP-0026021-3, "RES, 150 k, 1%, 0.063 W, AEC-Q200 Grade 0, 0402", Manufacturer=Vishay-Dale, Power_W=63mW, Supplier Part Number 1=541-150KLCT-ND, TempCo="100 ppm/C", Tolerance_%=1%, Value2=0.063W, Value_Code=150k
R16 R17: library part CMP-0026728-1, "RES, 220 k, 1%, 0.0625 W, 0402", Manufacturer="Yageo America", Power_W=62.5mW, Supplier Part Number 1=311-220KLRCT-ND, TempCo="100 ppm/C", Tolerance_%=1%, Value2=0.0625W, Value_Code=220k
R18: library part CMP-0081856-1, "RES, 0, 0%, 0.2 W, AEC-Q200 Grade 0, 0402", Manufacturer=Vishay-Dale, Power_W=200mW, Supplier Part Number 1=541-0.0YBTR-ND, Tolerance_%=0%, Value2=0.2W, Value_Code=0
R19: library part CMP-0026935-3, "RES, 47 k, 5%, 0.063 W, AEC-Q200 Grade 0, 0402", Manufacturer=Vishay-Dale, Power_W=63mW, Supplier Part Number 1=541-47KJCT-ND, TempCo="200 ppm/C", Tolerance_%=5%, Value2=0.063W, Value_Code=47k0, ValueDisplayed=47k
R20: library part CMP-0025874-4, "RES, 0, 5%, 0.1 W, AEC-Q200 Grade 0, 0603", Manufacturer=Panasonic, Power_W=100mW, Supplier Part Number 1=P0.0GCT-ND, TempCo="600 ppm/C", Tolerance_%=5%, Value2=0.1W, Value_Code=0000, ValueDisplayed=0
R21 R22: library part CMP-0025697-4, "RES, 0, 5%, 0.1 W, AEC-Q200 Grade 0, 0603", Manufacturer=Vishay-Dale, Power_W=100mW, Supplier Part Number 1=541-0.0GCT-ND, TempCo="200 ppm/C", Tolerance_%=5%, Value2=0.1W, Value_Code=0000, ValueDisplayed=0
R23: library part CMP-0025925-5, "RES, 47 k, 5%, 0.1 W, 0603", Manufacturer=Yageo, Power_W=100mW, Supplier Part Number 1=311-47KGRCT-ND, TempCo="100 ppm/C", Tolerance_%=5%, Value2=0.1W, Value_Code=47k0, ValueDisplayed=47k
R24 R25: library part CMP-0025733-4, "RES, 1.5 k, 5%, 0.1 W, AEC-Q200 Grade 0, 0603", Manufacturer=Vishay-Dale, Power_W=100mW, Supplier Part Number 1=541-1.5KGCT-ND, TempCo="200 ppm/C", Tolerance_%=5%, Value2=0.1W, Value_Code=1k50, ValueDisplayed=1.5k
R26: library part CMP-0025814-4, "RES, 47 k, 5%, 0.1 W, AEC-Q200 Grade 0, 0603", Manufacturer=Vishay-Dale, Power_W=100mW, Supplier Part Number 1=541-47KGCT-ND, TempCo="200 ppm/C", Tolerance_%=5%, Value2=0.1W, Value_Code=47k0, ValueDisplayed=47k
R27: library part CMP-0001777-2, "Trimming Potentiometer, 50K, 0.5W, TH", Manufacturer=Bourns, Supplier Part Number 1=3352T-503LF-ND
R28 R29 R30 R33: library part CMP-0025785-4, "RES, 330, 5%, 0.1 W, AEC-Q200 Grade 0, 0603", Manufacturer=Vishay-Dale, Power_W=100mW, Supplier Part Number 1=541-330GCT-ND, TempCo="200 ppm/C", Tolerance_%=5%, Value2=0.1W, Value_Code=330R, ValueDisplayed=330
R31: library part CMP-0022458-4, "RES, 4.99 k, 1%, 0.1 W, AEC-Q200 Grade 0, 0603", Manufacturer=Vishay-Dale, Power_W=100mW, Supplier Part Number 1=541-4.99KHCT-ND, TempCo="100 ppm/C", Tolerance_%=1%, Value2=0.1W, Value_Code=4k99, ValueDisplayed=4.99k
R32: library part CMP-0025701-4, "RES, 10 k, 5%, 0.1 W, AEC-Q200 Grade 0, 0603", Manufacturer=Vishay-Dale, Power_W=100mW, Supplier Part Number 1=541-10KGCT-ND, TempCo="200 ppm/C", Tolerance_%=5%, Value2=0.1W, Value_Code=10k0, ValueDisplayed=10k
S1: library part CMP-0002134-3, "Switch, Tactile, SPST-NO, 0.05A, 12V, SMT", CurrentRating_mA=50A, Manufacturer="TE Connectivity", Supplier Part Number 1=450-1129-ND
SH-J1 SH-J2 SH-J3 SH-J4 SH-J5 SH-J6 SH-J7 SH-J10 SH-J11 SH-J12 SH-J13 SH-J14 SH-J15 SH-J16 SH-J17 SH-J18 SH-J19 SH-J20: library part CMP-0003761-2, "Shunt, 2.54mm, Gold, Black", Manufacturer="Wurth Elektronik", Supplier Part Number 1=732-2678-ND
TP1 TP12 TP13 TP14 TP15: library part CMP-0055153-2, "Test Point, Compact, SMT", Manufacturer="Keystone Electronics", Supplier Part Number 1=36-5016TR-ND
TP2 TP3 TP4 TP5 TP8 TP9 TP10 TP11 TP26 TP27: library part CMP-0003719-1, "Testpoint", Manufacturer="Texas Instruments"
TP6 TP7: "1mm Uninsulated Shorting Plug, 10.16mm spacing, TH", Manufacturer=Harwin, PartNumber=D3082-05, Supplier Part Number 1=952-1873-ND
TP16 TP17 TP18 TP19 TP20 TP21 TP22 TP23 TP24 TP25: library part CMP-0055139-2, "Test Point, Miniature, White, TH", Color=White, Manufacturer="Keystone Electronics", Supplier Part Number 1=36-5002-ND
U1: "16-Bit Ultra-Low-Power Microcontroller, 128KB Flash, 8KB RAM, USB, 12Bit ADC, 2 USCIs, 32Bit HW MPY, RGC0064B (VQFN-64)", Alternate Manufacturer="Texas Instruments", Alternate PartNumber=MSP430F5528IRGCR, Frequency(MHz)=25, Operating Temperature Range="-40 to 85 C", PartNumber=MSP430F5528IRGCT, Rating=Catalog, Temp Sensor=Yes
U2: library part CMP-0043099-3, "Low-Capacitance 2-Channel +/-15kV ESD Protection Array for High-Speed Data Interfaces, DRY0006A (USON-6)", Breakdown Voltage(Min)(V)=11, IO Capacitance(Typ)(pF)=1.5, IO Leakage Current(nA)=1, Manufacturer="Texas Instruments", Operating Temperature Range="-40 to 85 C", Rating=Catalog
U3: library part CMP-0036330-5, "Single Output High PSRR LDO, 500 mA, Fixed 3.3 V Output, 2.7 to 6.5 V Input, with Low IQ, 6-pin SON (DRV), -40 to 125 degC, Green (RoHS & no Sb/Br)", Manufacturer="Texas Instruments"
U4: library part CMP-0073793-1, "150-mA, 30-V, Ultra-Low IQ, Wide Input Low-Dropout Regulator with Reverse Current Protection, DBV0005A (SOT-23-5)", Alternate Manufacturer="Texas Instruments", Alternate PartNumber=TPS70933DBVT
U5: library part CMP-0039449-2, "MSP430G2x53, MSP430G2x13 Mixed Signal Microcontroller, PW0028A (TSSOP-28)", Alternate Manufacturer="Texas Instruments", Alternate PartNumber=MSP430G2553IPW28, Frequency(MHz)=16, Temp Sensor=Yes
U6: library part CMP-0094669-1, "Dual H-Bridge Motor Driver with Current Regulation", Manufacturer="Texas Instruments", Max Supply Voltage=11V, Min Supply Voltage=1.65V, Operating Temperature Range="-40°C to +150°C", Switching Frequency=100kHz
Y1: library part CMP-0085483-1, "Oscillator, 4 MHz, 700 ppm, 39 pF, SMD", Frequency_Fixed=4MHz, Frequency Tolerance="700 ppm", Load Capacitance="39 pF", Manufacturer=MuRata
ZZ1: library part CMP-0003616-3
ZZ2: library part CMP-0077236-1
ZZ3: library part CMP-0077237-1
ZZ4: library part CMP-0077238-1

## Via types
v1: diameter 25/25/25/25 (per signal layer), hole 12, Top Layer to Bottom Layer, 136 vias
v2: diameter 25/25/25/25 (per signal layer), hole 12, Top Layer to Bottom Layer, tented both sides, 85 vias

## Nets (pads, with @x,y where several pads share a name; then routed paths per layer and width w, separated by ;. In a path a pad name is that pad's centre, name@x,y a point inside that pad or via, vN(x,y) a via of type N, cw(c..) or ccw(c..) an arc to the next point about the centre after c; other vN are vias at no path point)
AIN1: J7.2 TP16.1 U6.16 | length 1887.9
  Top Layer w10: J7.2@1356.4,2213.34 1391.73,2213.34 TP16.1@1524.61,2346.22 ; U6.16@2174.17,1310.98 2182.24,1302.91 v2(2182.24,1240.16)
  Bottom Layer w10: TP16.1@1524.61,2346.22 1442.17,2263.78 1442.17,1781.5 1498.02,1725.64 1546.51,1725.64 1577.48,1694.67 1577.48,1648.11 1985.43,1240.16 v2(2182.24,1240.16)
AIN1_MCU: J7.1 U5.20 | length 661.9
  Top Layer w10: U5.20@727.36,2114.17 727.36,2152.96 871.1,2296.7 1173.04,2296.7 J7.1@1256.4,2213.34
AIN2: J7.4 TP17.1 U6.15 | length 1713.8
  Top Layer w10: J7.4@1356.4,2113.34 1426.42,2113.34 TP17.1@1524.61,2211.53 ; v2(2148.78,1268.7) 2148.78,1276.35 2121.78,1303.35 2121.78,1323.95 2134.4,1336.57 U6.15@2174.17,1336.57
  Bottom Layer w10: TP17.1@1524.61,2211.53 1460.04,2146.96 1460.04,1788.9 1505.43,1743.52 1553.91,1743.52 1595.35,1702.07 1595.35,1655.51 1982.17,1268.7 v2(2148.78,1268.7)
AIN2_MCU: J7.3 U5.19 | length 653.3
  Top Layer w10: U5.19@752.95,2114.17 752.95,2153.27 866.68,2267 1102.74,2267 J7.3@1256.4,2113.34
AIPROPI: C34.1 J6.1 J7.14 R24.2 TP22.1 U6.14 | length 1870.3
  Top Layer w10: J7.14@1356.4,1613.34 1449.34,1613.34 TP22.1@1524.61,1538.08 ; R24.2@2086.73,1359.68 2094.23,1359.68 2095.47,1360.92 2125.05,1360.92 ; v2(2123.19,1383.21) 2125.05,1381.35 2125.05,1360.92 ; U6.14@2174.17,1362.16 2172.93,1360.92 2125.05,1360.92
  Signal Layer 2 w10: TP22.1@1524.61,1538.08 1586.57,1538.08 1741.44,1383.21 v2(2123.19,1383.21) 2202.08,1304.31 2543.8,1304.31 2590.04,1350.55 J6.1@2922,1350.55
  Bottom Layer w10: C34.1@2086.05,1361.82 2087.04,1361.82 2105.55,1380.34 2120.32,1380.34 v2(2123.19,1383.21)
AIPROPI_MCU: J7.13 U5.7 | length 747.3
  Top Layer w10: U5.7@676.18,1881.89 676.18,1787.22 779.03,1684.37 779.03,1683.76 837.43,1625.35 1169.66,1625.35 1181.67,1613.34 J7.13@1256.4,1613.34
AOUT1: C37.1 C41.1 J8.1 TP12.1 U6.2 | length 236.3
  Top Layer w15: TP12.1@3126,660 TP12.1@3126,721.5
  Bottom Layer w15: C37.1@2994,956.44 2994,891.56 C41.1@2997.56,888 3100.85,888 J8.1@3102,889.15
AOUT2: C37.2 C38.1 J8.2 TP13.1 U6.4 | length 236.4
  Top Layer w15: TP13.1@3126,1250.67 TP13.1@3126,1306.7
  Bottom Layer w15: C37.2@2994,1011.56 2994,1082.44 C38.1@2997.56,1086 J8.2@3102,1086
